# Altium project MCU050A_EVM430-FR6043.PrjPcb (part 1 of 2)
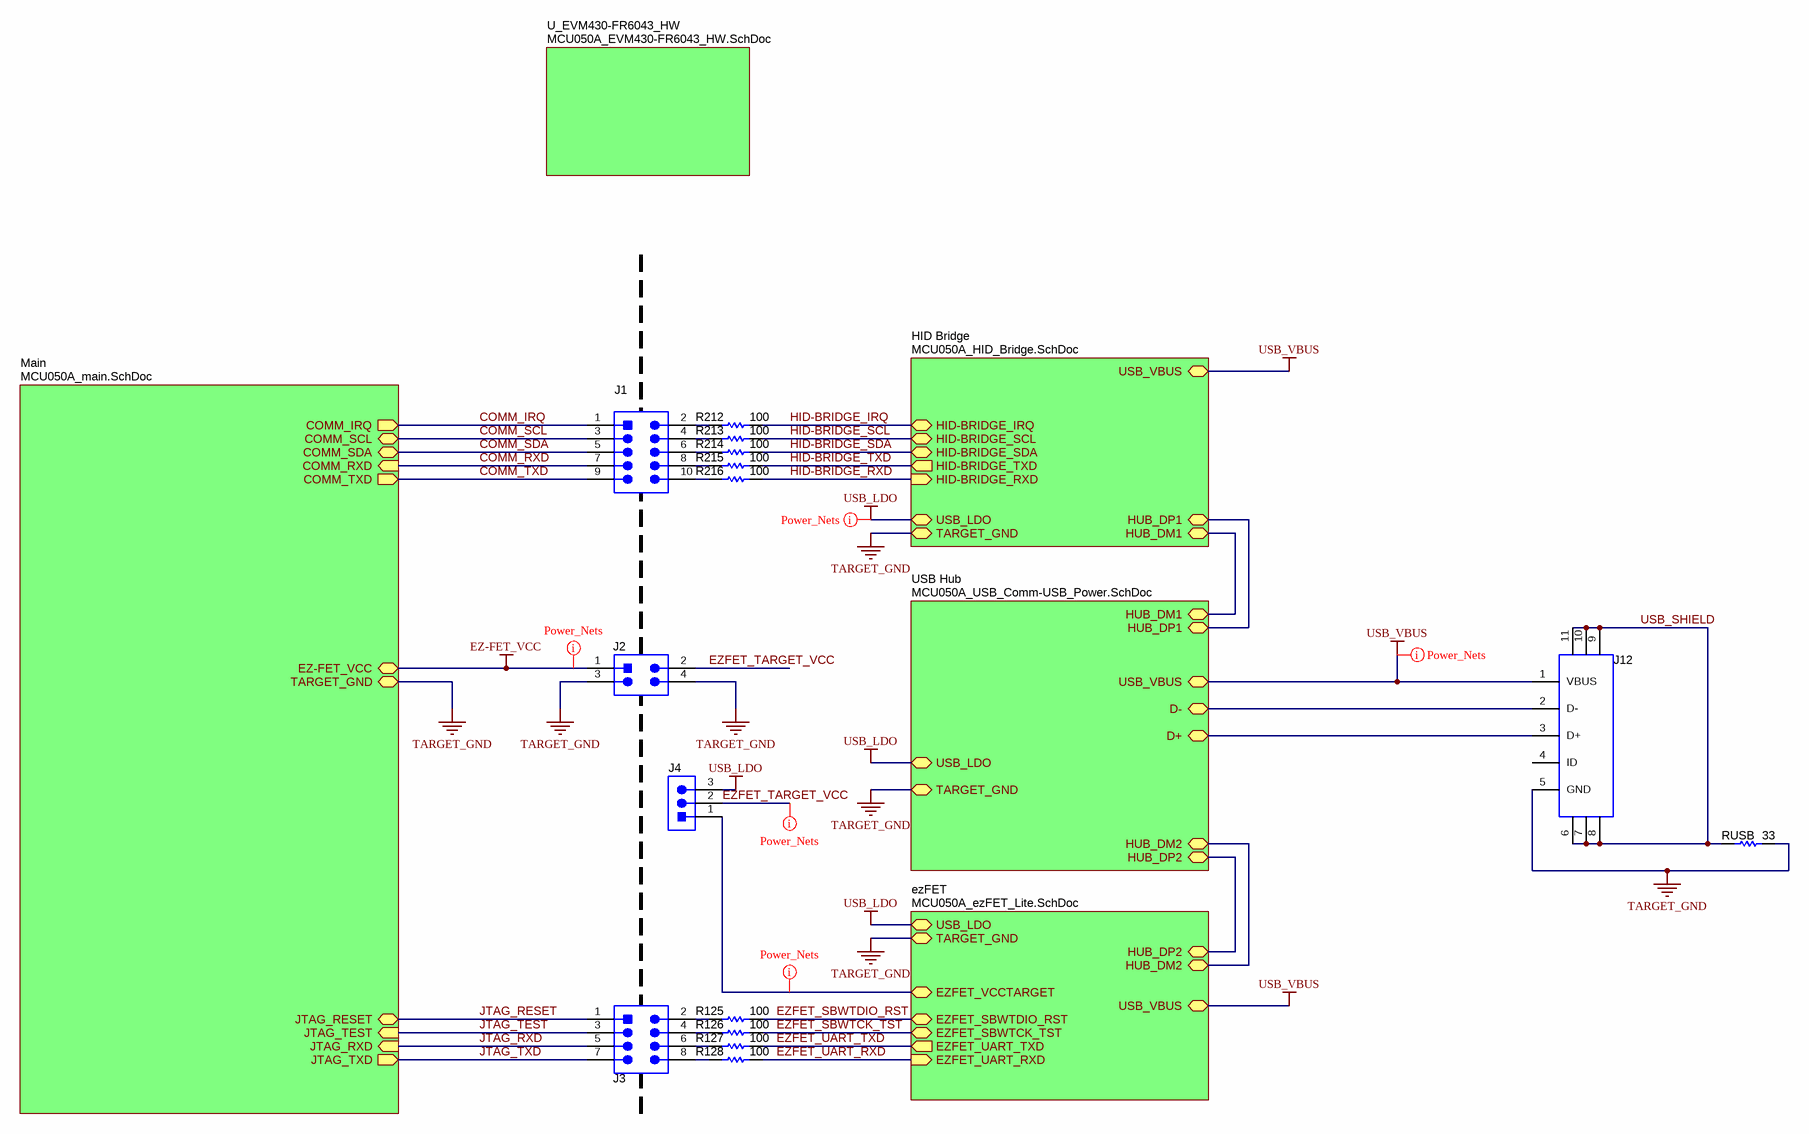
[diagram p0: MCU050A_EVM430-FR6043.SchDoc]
CopyrightYear: 2017; PCB_Layout: D. Garcia; PCB_Rev: A; PRJ_Customer: Public Release; PRJ_Engineer: D. Garcia; PRJ_Number: MCU050; PRJ_Title: EVM430-FR6043; SCH_Rev: A; TechSupport: http://www.ti.com/support; TID: N/A
7 sheets, 336 parts. Net scope: hierarchical (ports join the sheet entries above them; power ports are global).
Board file: MCU050A_EVM430-FR6043.PcbDoc
Sheets:
  MCU050A_EVM430-FR6043.SchDoc
    U_EVM430-FR6043_HW = MCU050A_EVM430-FR6043_HW.SchDoc
    Main = MCU050A_main.SchDoc
      AFE = MCU050A_Analog-Front-End.SchDoc
    HID Bridge = MCU050A_HID_Bridge.SchDoc
    USB Hub = MCU050A_USB_Comm-USB_Power.SchDoc
    ezFET = MCU050A_ezFET_Lite.SchDoc

## Sheet MCU050A_EVM430-FR6043.SchDoc
size 431 x 279 mm; Date: Not shown in title block; ApprovedBy: Not shown in title block; CheckedBy: Not shown in title block; Author: Not shown in title block; CompanyName: Not shown in title block; Engineer: Not shown in title block; Organization: Not shown in title block; Address1: Not shown in title block; Address2: Not shown in title block; Address3: Not shown in title block; Address4: Not shown in title block; DocumentNumber: 1; Revision: Use project parameter SCH_Rev; SheetNumber: 1; SheetTotal: 7; PageSetup: Record=PageOptions¦CenterHorizontal=True¦CenterVertical=True¦PrintScale=1.00¦XCorrection=1.00¦YCorrection=1.00¦PrintKind=0¦BorderSize=5000000¦LeftOffset=0¦BottomOffset=0¦Orientation=2¦PaperLength=1000¦PaperWidth=1000¦Scale=100¦PaperSource=15¦PrintQuality=600¦MediaType=1¦DitherType=10¦PaperKind=Letter¦PrintScaleMode=1

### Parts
J1  TSW-105-07-G-D  [TSW-105-07-G-D]  (value not drawn)
J2  PBC02DAAN  [Sullins_PxC02DAAN]  (value not drawn)
J3  PEC04DAAN  [CONN_PEC04DAAN]  (value not drawn)
J4  61300311121  [WURTH_61300311121]  (value not drawn)
J12  1051640001  [Molex_1051640001]  (value not drawn)
R125  ValueDisplayed: 100  [0402S]  (hidden comment: CRCW0402100RJNED)
R126  ValueDisplayed: 100  [0402S]  (hidden comment: CRCW0402100RJNED)
R127  ValueDisplayed: 100  [0402S]  (hidden comment: CRCW0402100RJNED)
R128  ValueDisplayed: 100  [0402S]  (hidden comment: CRCW0402100RJNED)
R212  ValueDisplayed: 100  [0402S]  (hidden comment: CRCW0402100RJNED)
R213  ValueDisplayed: 100  [0402S]  (hidden comment: CRCW0402100RJNED)
R214  ValueDisplayed: 100  [0402S]  (hidden comment: CRCW0402100RJNED)
R215  ValueDisplayed: 100  [0402S]  (hidden comment: CRCW0402100RJNED)
R216  ValueDisplayed: 100  [0402S]  (hidden comment: CRCW0402100RJNED)
RUSB  value 33  [0402S]  (hidden comment: CRCW040233R0JNED)

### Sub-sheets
ezFET = MCU050A_ezFET_Lite.SchDoc: EZFET_SBWTDIO_RST (bidir), EZFET_SBWTCK_TST (bidir), EZFET_UART_TXD (out), EZFET_UART_RXD (in), HUB_DP2 (bidir), HUB_DM2 (bidir), USB_VBUS, TARGET_GND, USB_LDO, EZFET_VCCTARGET
HID Bridge = MCU050A_HID_Bridge.SchDoc: HID-BRIDGE_TXD (out), HID-BRIDGE_RXD (in), HID-BRIDGE_SCL (bidir), HID-BRIDGE_SDA (bidir), HID-BRIDGE_IRQ (bidir), USB_VBUS, USB_LDO, TARGET_GND, HUB_DM1 (bidir), HUB_DP1 (bidir)
Main = MCU050A_main.SchDoc: COMM_RXD (in), COMM_TXD (out), COMM_SCL (bidir), COMM_SDA (bidir), EZ-FET_VCC, TARGET_GND, COMM_IRQ (out), JTAG_TXD (out), JTAG_RXD (in), JTAG_TEST (in), JTAG_RESET (bidir)
U_EVM430-FR6043_HW = MCU050A_EVM430-FR6043_HW.SchDoc: no entries
USB Hub = MCU050A_USB_Comm-USB_Power.SchDoc: HUB_DM1 (bidir), HUB_DP1 (bidir), HUB_DP2 (bidir), HUB_DM2 (bidir), USB_LDO, USB_VBUS, D- (bidir), D+ (bidir), TARGET_GND

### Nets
EZ-FET_VCC: J2.1 ; sheet Main/EZ-FET_VCC
TARGET_GND: J2.3 J2.4 J12.5(GND) RUSB.1 ; sheet Main/TARGET_GND, sheet HID Bridge/TARGET_GND, sheet USB Hub/TARGET_GND, sheet ezFET/TARGET_GND
USB_LDO: J4.3 ; sheet HID Bridge/USB_LDO, sheet USB Hub/USB_LDO, sheet ezFET/USB_LDO
USB_VBUS: J12.1(VBUS) ; sheet HID Bridge/USB_VBUS, sheet USB Hub/USB_VBUS, sheet ezFET/USB_VBUS
COMM_IRQ: J1.1 ; sheet Main/COMM_IRQ
COMM_RXD: J1.7 ; sheet Main/COMM_RXD
COMM_SCL: J1.3 ; sheet Main/COMM_SCL
COMM_SDA: J1.5 ; sheet Main/COMM_SDA
COMM_TXD: J1.9 ; sheet Main/COMM_TXD
D+: J12.3(D+) ; sheet USB Hub/D+
D-: J12.2(D-) ; sheet USB Hub/D-
EZFET_SBWTCK_TST: R126.1 ; sheet ezFET/EZFET_SBWTCK_TST
EZFET_SBWTDIO_RST: R125.1 ; sheet ezFET/EZFET_SBWTDIO_RST
EZFET_TARGET_VCC: J2.2 J4.2
EZFET_UART_RXD: R128.1 ; sheet ezFET/EZFET_UART_RXD
EZFET_UART_TXD: R127.1 ; sheet ezFET/EZFET_UART_TXD
EZFET_VCCTARGET: J4.1 ; sheet ezFET/EZFET_VCCTARGET
HID-BRIDGE_IRQ: R212.1 ; sheet HID Bridge/HID-BRIDGE_IRQ
HID-BRIDGE_RXD: R216.1 ; sheet HID Bridge/HID-BRIDGE_RXD
HID-BRIDGE_SCL: R213.1 ; sheet HID Bridge/HID-BRIDGE_SCL
HID-BRIDGE_SDA: R214.1 ; sheet HID Bridge/HID-BRIDGE_SDA
HID-BRIDGE_TXD: R215.1 ; sheet HID Bridge/HID-BRIDGE_TXD
HUB_DM1: sheet HID Bridge/HUB_DM1, sheet USB Hub/HUB_DM1
HUB_DM2: sheet USB Hub/HUB_DM2, sheet ezFET/HUB_DM2
HUB_DP1: sheet HID Bridge/HUB_DP1, sheet USB Hub/HUB_DP1
HUB_DP2: sheet USB Hub/HUB_DP2, sheet ezFET/HUB_DP2
JTAG_RESET: J3.1 ; sheet Main/JTAG_RESET
JTAG_RXD: J3.5 ; sheet Main/JTAG_RXD
JTAG_TEST: J3.3 ; sheet Main/JTAG_TEST
JTAG_TXD: J3.7 ; sheet Main/JTAG_TXD
USB_SHIELD: J12.6 J12.7 J12.8 J12.9 J12.10 J12.11 RUSB.2
NetJ1_2: J1.2 R212.2
NetJ1_4: J1.4 R213.2
NetJ1_6: J1.6 R214.2
NetJ1_8: J1.8 R215.2
NetJ1_10: J1.10 R216.2
NetJ3_2: J3.2 R125.2
NetJ3_4: J3.4 R126.2
NetJ3_6: J3.6 R127.2
NetJ3_8: J3.8 R128.2

Not connected (* = marked no-connect by the designer): J12 4(ID)

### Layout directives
net class Power_Nets: EZ-FET_VCC, EZFET_TARGET_VCC, EZFET_VCCTARGET, USB_LDO, USB_VBUS

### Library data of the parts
J1 = TSW-105-07-G-D: Header, 100mil, 5x2, Gold, TH; Manufacturer: Samtec; SymbolCreator: a0412235; Pitch_mm: 2.54; Gender: Male; Shrouded: N; Row_Count: 2; Current_A: 6.3; Voltage_V: 550; Cert_CSA: Y; Green_Lifecycle: Active; Green_REACh: Passed
J2 = PBC02DAAN: Header, 2.54mm, 2x2, Gold, TH; Manufacturer: Sullins Connector Solutions; SymbolCreator: a0412235; Pitch_mm: 2.54; Gender: Male; Shrouded: N; Row_Count: 2; Current_A: 3; Voltage_V: 1800; Cert_UL: Y
J3 = PEC04DAAN: Header, 100mil, 4x2, Tin, TH; Manufacturer: Sullins Connector Solutions; SymbolCreator: a0411947; Pitch_mm: 2.54; Gender: Male; Shrouded: N; Row_Count: 2; Current_A: 3; Voltage_V: 1800; Cert_UL: Y; Green_Lifecycle: Not Set; Green_REACh: Incomplete
J4 = 61300311121: Header, 2.54 mm, 3x1, Gold, TH; Manufacturer: Wurth Elektronik; SymbolCreator: a0799628; Green_Lifecycle: Active; Green_REACh: Passed
J12 = 1051640001: Receptacle, USB 2.0, Micro B, 5 Position, R/A, SMT; Manufacturer: Molex; SymbolCreator: a0411947; Pitch_mm: 0.65; Gender: Female; ContactFinish: Gold; Current_A: 1.8; Voltage_V: 30; Cert_UL: Y
R125-R128 R212-R216 = CRCW0402100RJNED: RES, 100, 5%, 0.063 W, 0402; Manufacturer: Vishay-Dale; CompType: Resistor; Value: 100; Value_Code: 100R; Tolerance_%: 5; Power_W: 0.063; Value2: 0.063W; VDC_V: 50; TempCo: 200 ppm/C; EIA_Code: E24; U/M: EA; AEC Category: Q200
RUSB = CRCW040233R0JNED: RES, 33 ohm, 5%, 0.063W, 0402; Manufacturer: Vishay-Dale; CompType: Resistor; Value_Code: 33R0; Tolerance_%: 5; Power_W: 0.063; VDC_V: 50; TempCo: 200 ppm/C; EIA_Code: E24; U/M: EA

## Sheet MCU050A_EVM430-FR6043_HW.SchDoc
size 431 x 279 mm; Date: Not shown in title block; ApprovedBy: Not shown in title block; CheckedBy: Not shown in title block; Author: Not shown in title block; CompanyName: Not shown in title block; DrawnBy: Michael Schneider; Engineer: Not shown in title block; Organization: Not shown in title block; Address1: Not shown in title block; Address2: Not shown in title block; Address3: Not shown in title block; Address4: Not shown in title block; DocumentNumber: 1; Revision: Use project parameter SCH_Rev; SheetNumber: 7; SheetTotal: 7; PageSetup: Record=PageOptions¦CenterHorizontal=True¦CenterVertical=True¦PrintScale=1.00¦XCorrection=1.00¦YCorrection=1.00¦PrintKind=0¦BorderSize=5000000¦LeftOffset=0¦BottomOffset=0¦Orientation=2¦PaperLength=1000¦PaperWidth=1000¦Scale=100¦PaperSource=15¦PrintQuality=600¦MediaType=1¦DitherType=10¦PaperKind=Letter¦PrintScaleMode=1
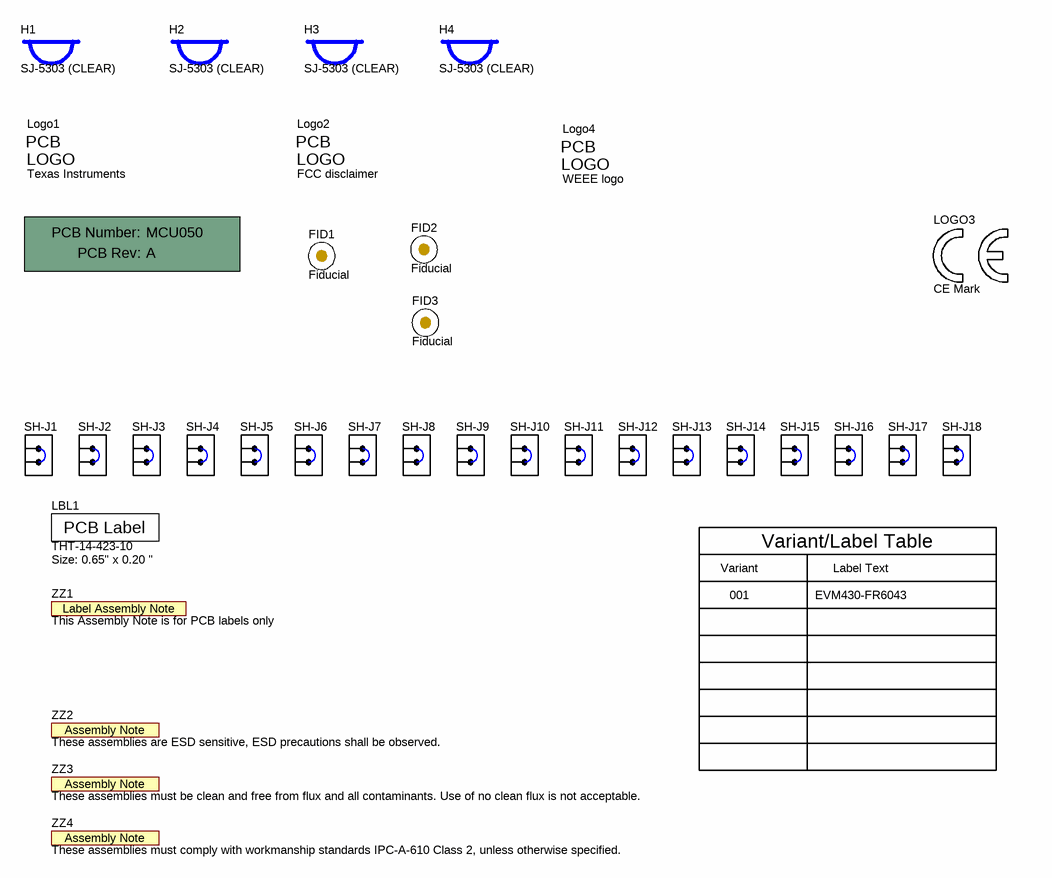
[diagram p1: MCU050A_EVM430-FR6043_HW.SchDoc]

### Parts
!PCB  Printed Circuit Board  (value not drawn)  (mechanical)
FID1  Fiducial  [Fiducial10-30]
FID2  Fiducial  [Fiducial10-30]
FID3  Fiducial  [Fiducial10-30]
H1  SJ-5303 (CLEAR)  [Bumpon_SJ5003Transparent]
H2  SJ-5303 (CLEAR)  [Bumpon_SJ5003Transparent]
H3  SJ-5303 (CLEAR)  [Bumpon_SJ5003Transparent]
H4  SJ-5303 (CLEAR)  [Bumpon_SJ5003Transparent]
LBL1  THT-14-423-10  Note: Size: 0.65" x 0.20 "  [Label_650x200]
Logo1  Texas Instruments  [TI_Stacked_Overlay_Small]  (no BOM)
Logo2  FCC disclaimer  [FCC_disclaimer]  (no BOM)
LOGO3  CE Mark  [CE_Mark_5mm]  (no BOM)
Logo4  WEEE logo  [WEEE_Minimum]  (no BOM)
SH-J1  60900213421  [Wurth_60900213421]  (value not drawn)
SH-J2  60900213421  [Wurth_60900213421]  (value not drawn)
SH-J3  60900213421  [Wurth_60900213421]  (value not drawn)
SH-J4  60900213421  [Wurth_60900213421]  (value not drawn)
SH-J5  60900213421  [Wurth_60900213421]  (value not drawn)
SH-J6  60900213421  [Wurth_60900213421]  (value not drawn)
SH-J7  60900213421  [Wurth_60900213421]  (value not drawn)
SH-J8  60900213421  [Wurth_60900213421]  (value not drawn)
SH-J9  60900213421  [Wurth_60900213421]  (value not drawn)
SH-J10  60900213421  [Wurth_60900213421]  (value not drawn)
SH-J11  60900213421  [Wurth_60900213421]  (value not drawn)
SH-J12  60900213421  [Wurth_60900213421]  (value not drawn)
SH-J13  60900213421  [Wurth_60900213421]  (value not drawn)
SH-J14  60900213421  [Wurth_60900213421]  (value not drawn)
SH-J15  60900213421  [Wurth_60900213421]  (value not drawn)
SH-J16  60900213421  [Wurth_60900213421]  (value not drawn)
SH-J17  60900213421  [Wurth_60900213421]  (value not drawn)
SH-J18  60900213421  [Wurth_60900213421]  (value not drawn)
ZZ1  This Assembly Note is for PCB labels only  [AssemblyNoteLabel]  (no BOM)
ZZ2  These assemblies are ESD sensitive, ESD precautions shall be observed.  [AssemblyNote]  (no BOM)
ZZ3  These assemblies must be clean and free from flux and all contaminants. Use of no clean flux is not acceptable.  [AssemblyNote]  (no BOM)
ZZ4  These assemblies must comply with workmanship standards IPC-A-610 Class 2, unless otherwise specified.  [AssemblyNote]  (no BOM)

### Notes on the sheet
- Variant/Label Table
- Variant
- 001
- Label Text
- EVM430-FR6043

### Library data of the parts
!PCB = PCB: Manufacturer: Any; PartNumber: MCU050; SymbolCreator: a0412235
FID1-FID3 = CMP-0077181-1: Fiducial mark.  There is nothing to buy or mount.
H1-H4 = SJ-5303 (CLEAR): Bumpon, Hemisphere, 0.44 X 0.20, Clear; Manufacturer: 3M; SymbolCreator: a0412235
LBL1 = CMP-0003625-1: Thermal Transfer Printable Labels, 0.650" W x 0.200" H - 10,000 per roll; Manufacturer: Brady; CompType: Label
Logo1 = TI_Logo: Texas Instrument Corporate Signature; SymbolCreator: codlsc
Logo2 = FCC_disclaimer: SymbolCreator: codlsc
LOGO3 = CMP-0074844-1: SymbolCreator: a0412235
Logo4 = CMP-0074769-1
SH-J1-SH-J18 = CMP-0003761-2: Shunt, 2.54mm, Gold, Black; Manufacturer: Wurth Elektronik
ZZ1 = AssemblyNoteLabel: SymbolCreator: a0412235
ZZ2-ZZ4 = AssemblyNote: SymbolCreator: codlsc

## Sheet MCU050A_main.SchDoc
size 558 x 381 mm; Date: Not shown in title block; ApprovedBy: Not shown in title block; CheckedBy: Not shown in title block; Author: Not shown in title block; CompanyName: Not shown in title block; Engineer: Not shown in title block; Organization: Not shown in title block; Address1: Not shown in title block; Address2: Not shown in title block; Address3: Not shown in title block; Address4: Not shown in title block; DocumentNumber: 1; Revision: Use project parameter SCH_Rev; SheetNumber: 2; SheetTotal: 7; PageSetup: Record=PageOptions¦CenterHorizontal=True¦CenterVertical=True¦PrintScale=1.00¦XCorrection=1.00¦YCorrection=1.00¦PrintKind=0¦BorderSize=5000000¦LeftOffset=0¦BottomOffset=0¦Orientation=2¦PaperLength=1000¦PaperWidth=1000¦Scale=100¦PaperSource=15¦PrintQuality=600¦MediaType=1¦DitherType=10¦PaperKind=Letter¦PrintScaleMode=1
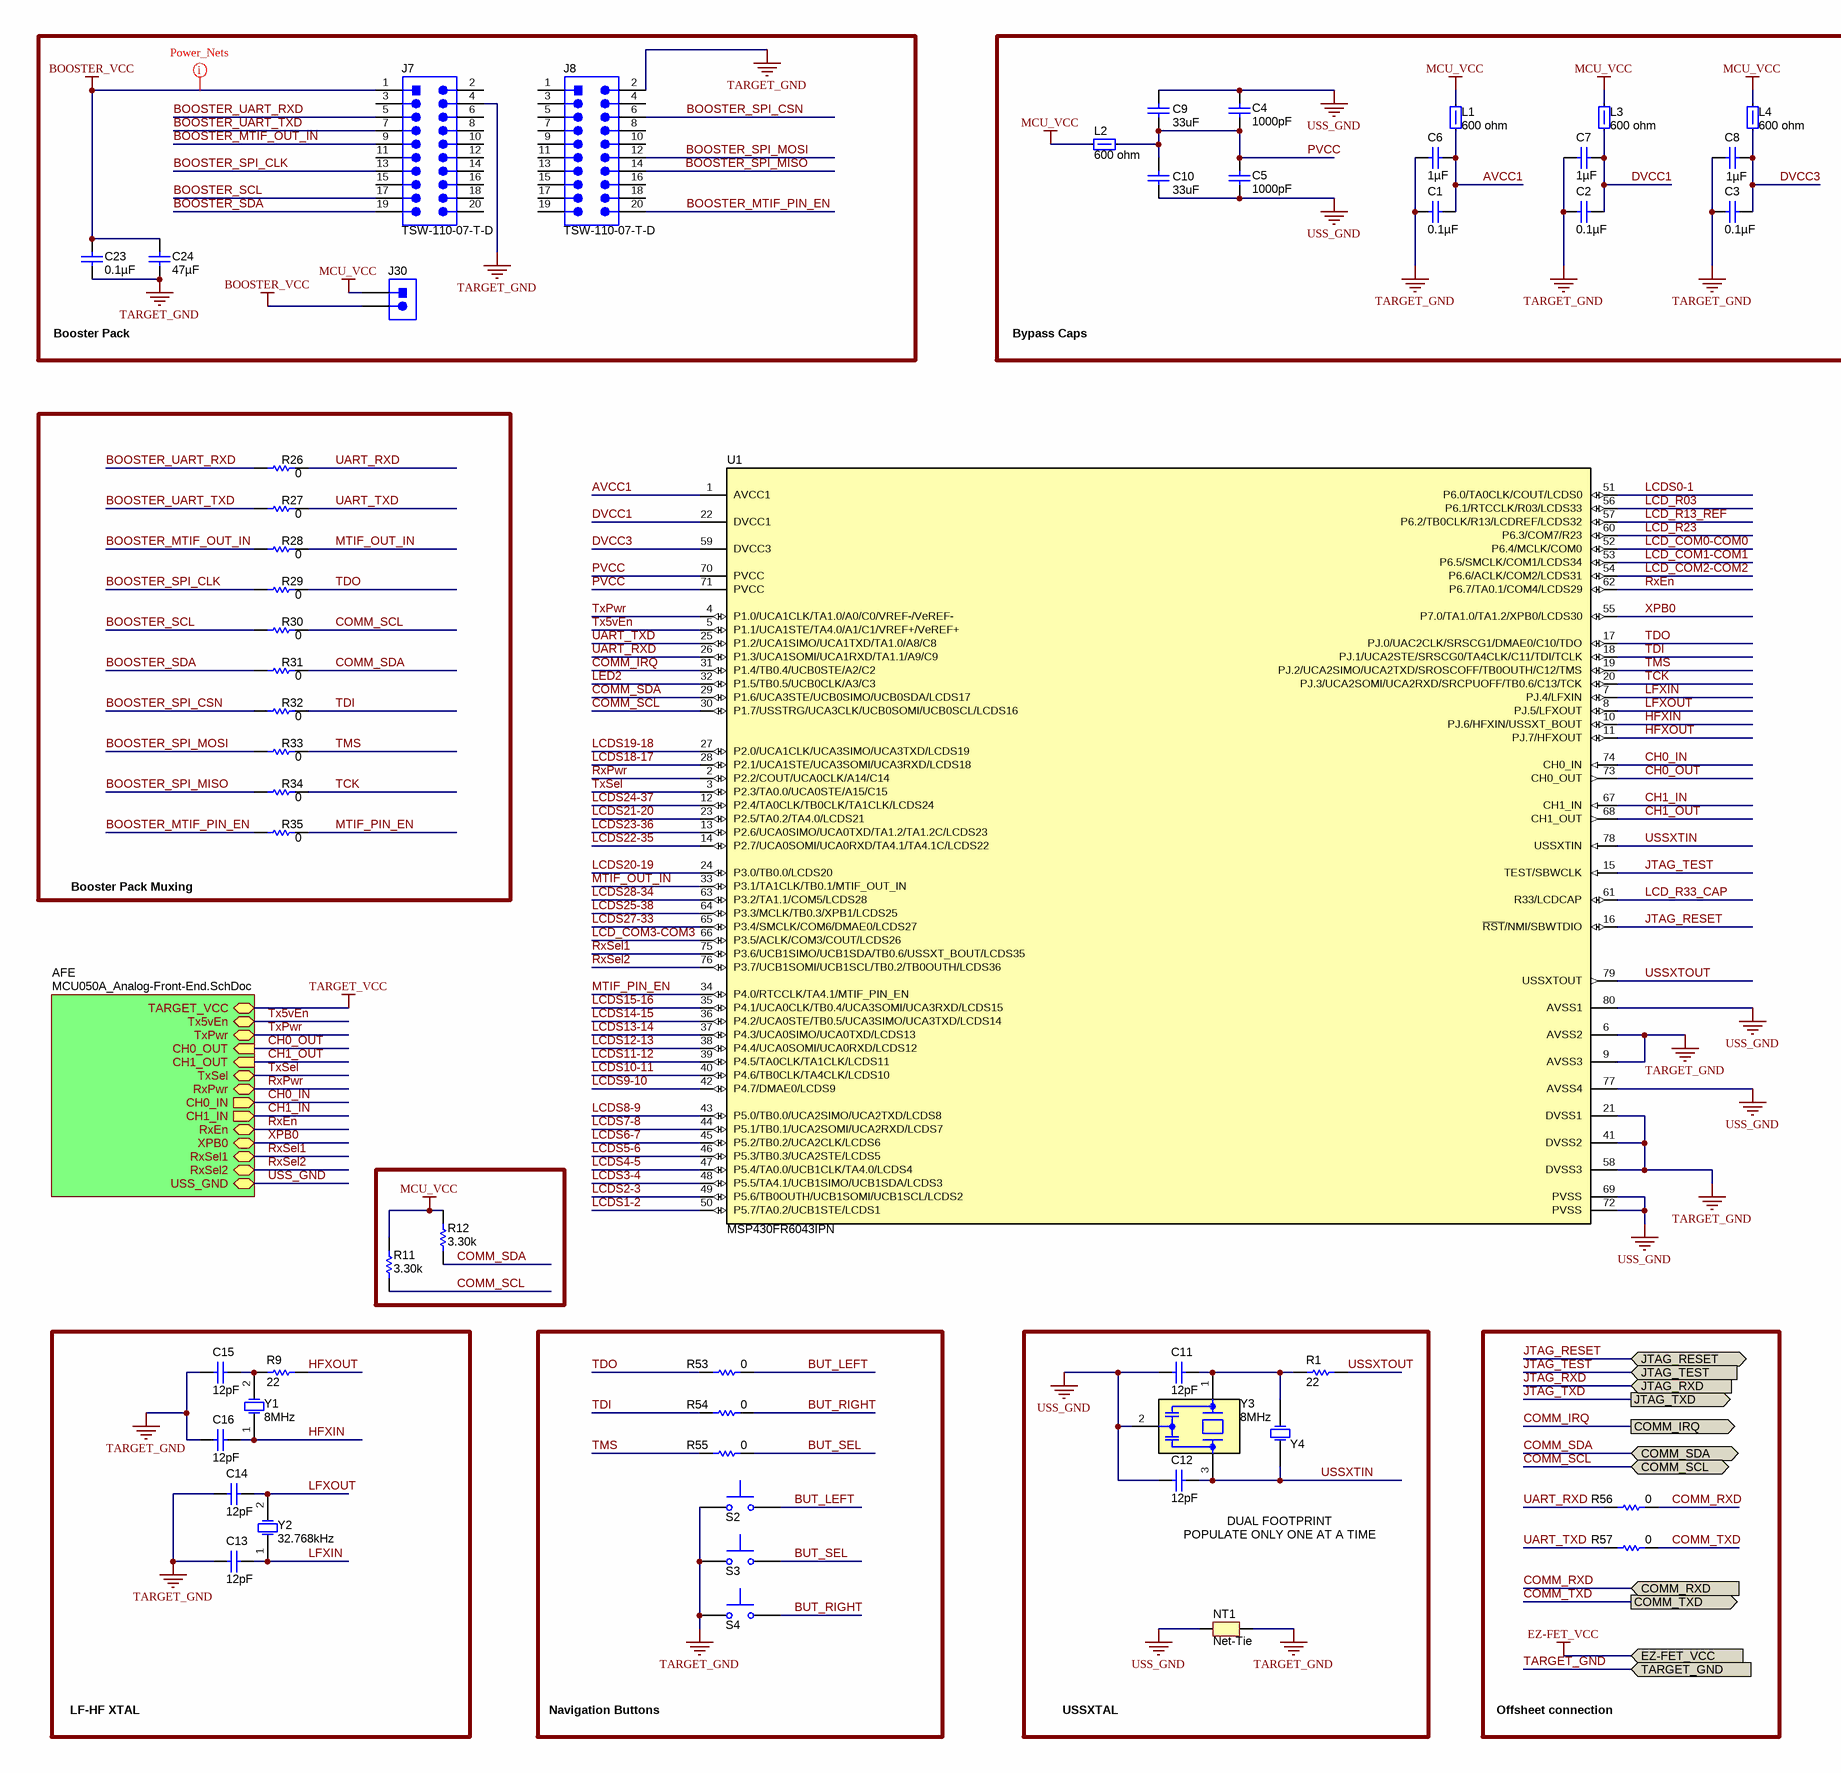
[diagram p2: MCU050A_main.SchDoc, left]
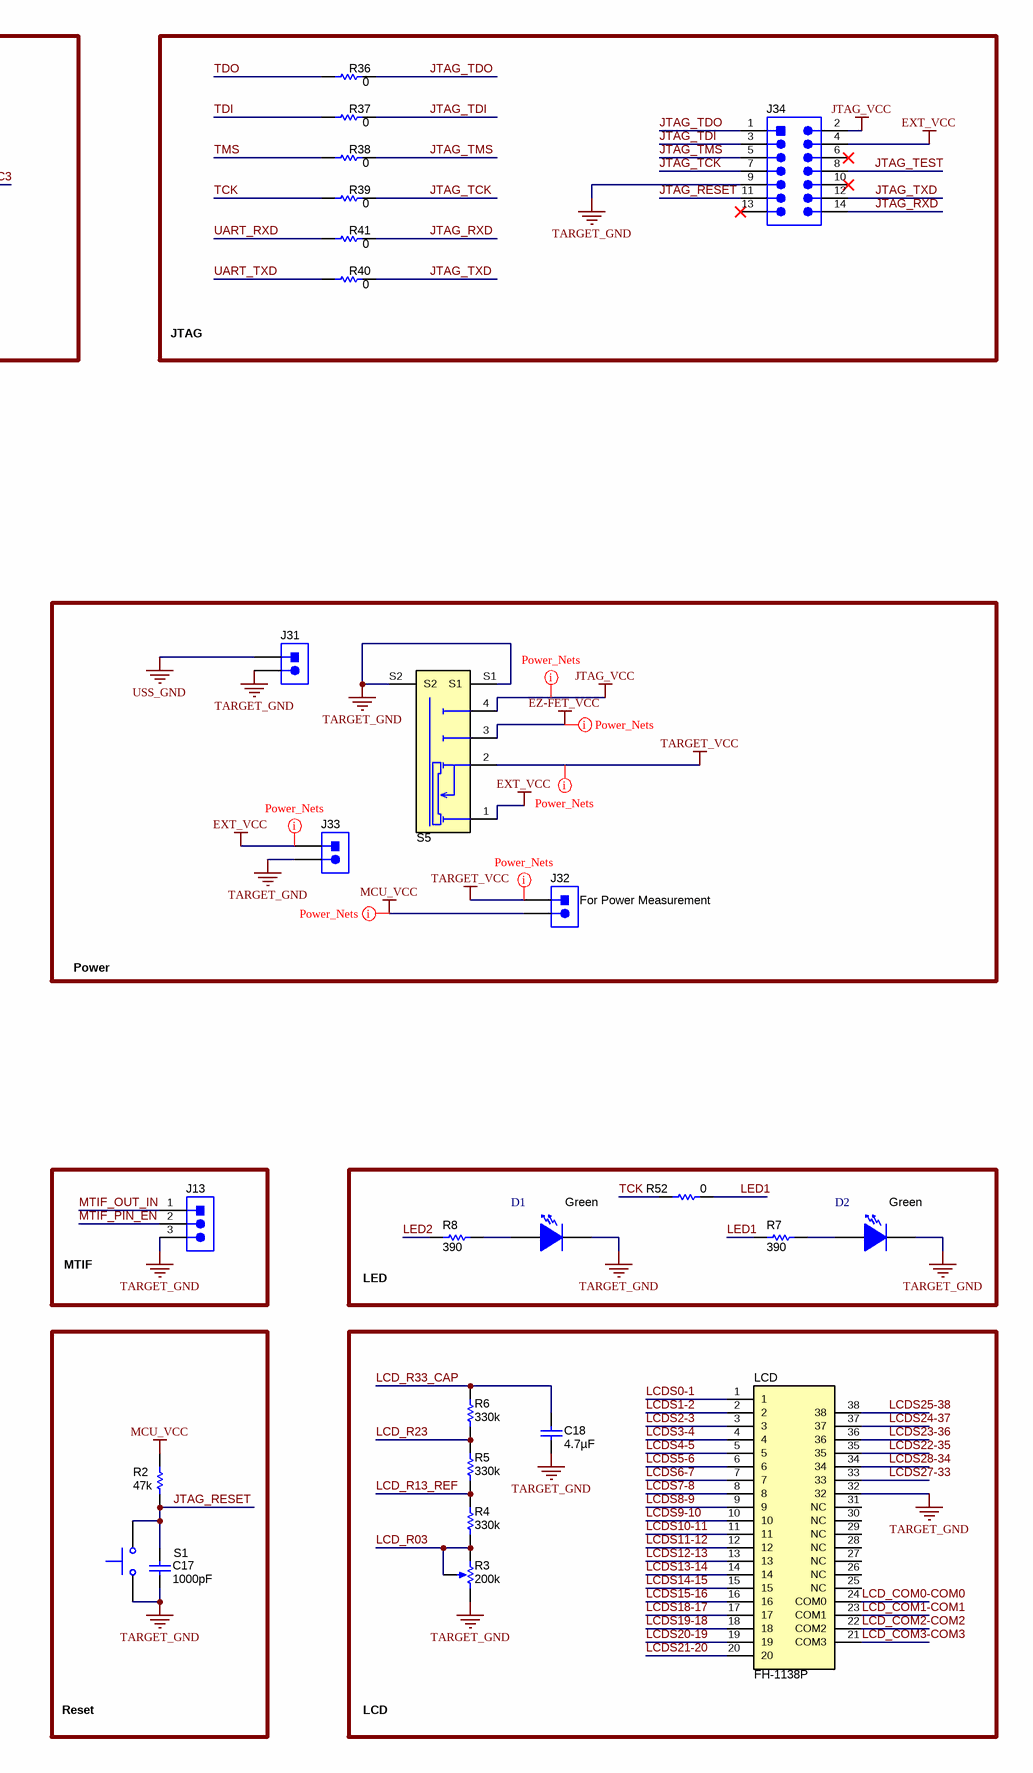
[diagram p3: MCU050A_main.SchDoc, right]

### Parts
C1  ValueDisplayed: 0.1µF  [0402S]  (hidden comment: GRM155R71C104KA88D)
C2  ValueDisplayed: 0.1µF  [0402S]  (hidden comment: GRM155R71C104KA88D)
C3  ValueDisplayed: 0.1µF  [0402S]  (hidden comment: GRM155R71C104KA88D)
C4  ValueDisplayed: 1000pF  [0402S]  (hidden comment: GRM1555C1H102JA01D)
C5  ValueDisplayed: 1000pF  [0402S]  (hidden comment: GRM1555C1H102JA01D)
C6  ValueDisplayed: 1µF  [0603S]  (hidden comment: GRM188R71A105KA61D)
C7  ValueDisplayed: 1µF  [0603S]  (hidden comment: GRM188R71A105KA61D)
C8  ValueDisplayed: 1µF  [0603S]  (hidden comment: GRM188R71A105KA61D)
C9  ValueDisplayed: 33uF  [0805]  (hidden comment: C2012X5R1A336M125AC)
C10  ValueDisplayed: 33uF  [0805]  (hidden comment: C2012X5R1A336M125AC)
C11  ValueDisplayed: 12pF  [0402]  (hidden comment: GRM1555C1H120JA01D)
C12  ValueDisplayed: 12pF  [0402]  (hidden comment: GRM1555C1H120JA01D)
C13  ValueDisplayed: 12pF  [0402S]  (hidden comment: GRM1555C1H120JA01D)
C14  ValueDisplayed: 12pF  [0402S]  (hidden comment: GRM1555C1H120JA01D)
C15  ValueDisplayed: 12pF  [0402]  (hidden comment: GRM1555C1H120JA01D)
C16  ValueDisplayed: 12pF  [0402]  (hidden comment: GRM1555C1H120JA01D)
C17  ValueDisplayed: 1000pF  [0402S]  (hidden comment: GRM1555C1H102JA01D)
C18  ValueDisplayed: 4.7µF  [0603M]  (hidden comment: GRM188R61A475MAAJ)
C23  ValueDisplayed: 0.1µF  [0402]  (hidden comment: GRM155R71C104KA88D)
C24  ValueDisplayed: 47µF  [0805_HV]  (hidden comment: GRM21BR60J476ME15L)
D1  value Green  [LTST-C191_Green]  (hidden comment: LTST-C191TGKT)
D2  value Green  [LTST-C191_Green]  (hidden comment: LTST-C191TGKT)
J7  TSW-110-07-T-D  [Samtec_TSW-110-07-x-D]
J8  TSW-110-07-T-D  [Samtec_TSW-110-07-x-D]
J13  61300311121  [WURTH_61300311121]  (value not drawn)
J30  61300211121  [WURTH_61300211121]  (value not drawn)
J31  61300211121  [WURTH_61300211121]  (value not drawn)
J32  61300211121  [WURTH_61300211121]  (value not drawn)
J33  61300211121  [WURTH_61300211121]  (value not drawn)
J34  SBH11-PBPC-D07-ST-BK  [CONN_SBH11-PBPC-D07-ST-BK]  (value not drawn)
L1  value 600 ohm  [0805L]  (hidden comment: MPZ2012S601A)
L2  value 600 ohm  [0805L]  (hidden comment: MPZ2012S601A)
L3  value 600 ohm  [0805L]  (hidden comment: MPZ2012S601A)
L4  value 600 ohm  [0805L]  (hidden comment: MPZ2012S601A)
LCD  FH-1138P  [ADKOM_FH-1138P]
NT1  Net-Tie  [Net-Tie_50milWide_30milLong]  (net tie, no BOM)
R1  ValueDisplayed: 22  [0402S]  (hidden comment: CRCW040222R0JNED)
R2  ValueDisplayed: 47k  [0402S]  (hidden comment: CRCW040247K0JNED)
R3  value 200k  [TRIM_3224W]  (hidden comment: 3224W-1-204E)
R4  ValueDisplayed: 330k  [0402S]  (hidden comment: CRCW0402330KJNED)
R5  ValueDisplayed: 330k  [0402S]  (hidden comment: CRCW0402330KJNED)
R6  ValueDisplayed: 330k  [0402S]  (hidden comment: CRCW0402330KJNED)
R7  ValueDisplayed: 390  [0402S]  (hidden comment: CRCW0402390RJNED)
R8  ValueDisplayed: 390  [0402S]  (hidden comment: CRCW0402390RJNED)
R9  ValueDisplayed: 22  [0402S]  (hidden comment: CRCW040222R0JNED)
R11  ValueDisplayed: 3.30k  [0402]  (hidden comment: ERJ-2RKF3301X)
R12  ValueDisplayed: 3.30k  [0402]  (hidden comment: ERJ-2RKF3301X)
R26  ValueDisplayed: 0  [0402S]  (hidden comment: CRCW04020000Z0ED)
R27  ValueDisplayed: 0  [0402S]  (hidden comment: CRCW04020000Z0ED)
R28  ValueDisplayed: 0  [0402S]  (hidden comment: CRCW04020000Z0ED)
R29  ValueDisplayed: 0  [0402S]  (hidden comment: CRCW04020000Z0ED)
R30  ValueDisplayed: 0  [0402S]  (hidden comment: CRCW04020000Z0ED)
R31  ValueDisplayed: 0  [0402S]  (hidden comment: CRCW04020000Z0ED)
R32  ValueDisplayed: 0  [0402S]  (hidden comment: CRCW04020000Z0ED)
R33  ValueDisplayed: 0  [0402S]  (hidden comment: CRCW04020000Z0ED)
R34  ValueDisplayed: 0  [0402S]  (hidden comment: CRCW04020000Z0ED)
R35  ValueDisplayed: 0  [0402S]  (hidden comment: CRCW04020000Z0ED)
R36  ValueDisplayed: 0  [0402S]  (hidden comment: CRCW04020000Z0ED)
R37  ValueDisplayed: 0  [0402S]  (hidden comment: CRCW04020000Z0ED)
R38  ValueDisplayed: 0  [0402S]  (hidden comment: CRCW04020000Z0ED)
R39  ValueDisplayed: 0  [0402S]  (hidden comment: CRCW04020000Z0ED)
R40  ValueDisplayed: 0  [0402S]  (hidden comment: CRCW04020000Z0ED)
R41  ValueDisplayed: 0  [0402S]  (hidden comment: CRCW04020000Z0ED)
R52  ValueDisplayed: 0  [0402S]  (hidden comment: CRCW04020000Z0ED)
R53  ValueDisplayed: 0  [0402S]  (hidden comment: CRCW04020000Z0ED)
R54  ValueDisplayed: 0  [0402S]  (hidden comment: CRCW04020000Z0ED)
R55  ValueDisplayed: 0  [0402S]  (hidden comment: CRCW04020000Z0ED)
R56  ValueDisplayed: 0  [0402S]  (hidden comment: CRCW04020000Z0ED)
R57  ValueDisplayed: 0  [0402S]  (hidden comment: CRCW04020000Z0ED)
S1  B3U-1000P  [SW_B3U-1000P]  (value not drawn)
S2  TL1015AF160QG  [SW_TL1015AF160QG]  (value not drawn)
S3  TL1015AF160QG  [SW_TL1015AF160QG]  (value not drawn)
S4  TL1015AF160QG  [SW_TL1015AF160QG]  (value not drawn)
S5  SS-13D16-VG 4 PA  [SW_SS-13D16-VG]  (value not drawn)
U1  MSP430FR6043IPN  [PN0080A_N]
Y1  Frequency: 8MHz  [Abracon_ABM3]  (hidden comment: ABM3-8.000MHZ-D2Y-T)
Y2  Frequency: 32.768kHz  [XTAL_ABS07]  (hidden comment: ABS07-32.768KHZ-9-T)
Y3  Frequency: 8MHz  [Abracon_AWSCR-CV]  (hidden comment: AWSCR-8.00CV-T)
Y4  ABLS-8.000MHZ-B4-T  [XTAL_CSM-7X]  (value not drawn)

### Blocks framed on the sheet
Booster Pack: C23 C24 J7 J8 J30
Bypass Caps: C1-C10 L1-L4
JTAG: J34 R36-R41
Booster Pack Muxing: R26-R35
MTIF: J13
LED: D1 D2 R7 R8 R52
LF-HF XTAL: C13-C16 R9 Y1 Y2
Navigation Buttons: R53-R55 S2-S4
Offsheet connection: R56 R57
Reset: C17 R2 S1
LCD: C18 LCD R3-R6

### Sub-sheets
AFE = MCU050A_Analog-Front-End.SchDoc: Tx5vEn (bidir), TxPwr (bidir), CH0_OUT (in), CH1_OUT (in), TxSel (bidir), RxPwr (bidir), CH0_IN (out), RxEn (bidir), XPB0 (bidir), RxSel1 (bidir), USS_GND, RxSel2 (bidir), CH1_IN (out), TARGET_VCC

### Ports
COMM_IRQ (out), COMM_RXD (in), COMM_SCL (bidir), COMM_SDA (bidir), COMM_TXD (out), EZ-FET_VCC, JTAG_RESET (bidir), JTAG_RXD (in), JTAG_TEST (in), JTAG_TXD (out), TARGET_GND

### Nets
BOOSTER_VCC: C23.1 C24.1 J7.1 J30.2
EXT_VCC: J33.1 J34.4 S5.1
EZ-FET_VCC: S5.3 ; port EZ-FET_VCC
JTAG_VCC: J34.2 S5.4
MCU_VCC: J30.1 J32.2 L1.2 L2.1 L3.2 L4.2 R2.2 R11.2 R12.2
TARGET_GND: C1.2 C2.1 C3.2 C6.2 C7.1 C8.1 C13.2 C14.1 C15.2 C16.2 C17.2 C18.2 C23.2 C24.2 D1.2(K) D2.2(K) J7.4 J8.2 J13.3 J31.2 J33.2 J34.9 LCD.32 NT1.2 R3.3(CW) S1.1 S2.1 S3.1 S4.1 S5.S1 S5.S2 U1.6(AVSS2) U1.9(AVSS3) U1.21(DVSS1) U1.41(DVSS2) U1.58(DVSS3) ; port TARGET_GND
TARGET_VCC: J32.1 S5.2 ; sheet AFE/TARGET_VCC
USS_GND: C4.1 C5.2 C9.1 C10.2 C11.2 C12.2 J31.1 NT1.1 U1.69(PVSS) U1.72(PVSS) U1.77(AVSS4) U1.80(AVSS1) Y3.2(GND) ; sheet AFE/USS_GND
AVCC1: C1.1 C6.1 L1.1 U1.1(AVCC1)
BOOSTER_MTIF_OUT_IN: J7.9 R28.2
BOOSTER_MTIF_PIN_EN: J8.20 R35.2
BOOSTER_SCL: J7.17 R30.2
BOOSTER_SDA: J7.19 R31.2
BOOSTER_SPI_CLK: J7.13 R29.2
BOOSTER_SPI_CSN: J8.6 R32.2
BOOSTER_SPI_MISO: J8.14 R34.2
BOOSTER_SPI_MOSI: J8.12 R33.2
BOOSTER_UART_RXD: J7.5 R26.2
BOOSTER_UART_TXD: J7.7 R27.2
BUT_LEFT: R53.1 S2.2
BUT_RIGHT: R54.1 S4.2
BUT_SEL: R55.1 S3.2
CH0_IN: U1.74(CH0_IN) ; sheet AFE/CH0_IN
CH0_OUT: U1.73(CH0_OUT) ; sheet AFE/CH0_OUT
CH1_IN: U1.67(CH1_IN) ; sheet AFE/CH1_IN
CH1_OUT: U1.68(CH1_OUT) ; sheet AFE/CH1_OUT
COMM_IRQ: U1.31(P1.4/TB0.4/UCB0STE/A2/C2) ; port COMM_IRQ
COMM_RXD: R56.1 ; port COMM_RXD
COMM_SCL: R11.1 R30.1 U1.30(P1.7/USSTRG/UCA3CLK/UCB0SOMI/UCB0SCL/LCDS16) ; port COMM_SCL
COMM_SDA: R12.1 R31.1 U1.29(P1.6/UCA3STE/UCB0SIMO/UCB0SDA/LCDS17) ; port COMM_SDA
COMM_TXD: R57.1 ; port COMM_TXD
DVCC1: C2.2 C7.2 L3.1 U1.22(DVCC1)
DVCC3: C3.1 C8.2 L4.1 U1.59(DVCC3)
HFXIN: C16.1 U1.10(PJ.6/HFXIN/USSXT_BOUT) Y1.1(OSC1)
HFXOUT: R9.2 U1.11(PJ.7/HFXOUT)
JTAG_RESET: C17.1 J34.11 R2.1 S1.2 U1.16(~{RST}/NMI/SBWTDIO) ; port JTAG_RESET
JTAG_RXD: J34.14 R41.1 ; port JTAG_RXD
JTAG_TCK: J34.7 R39.1
JTAG_TDI: J34.3 R37.1
JTAG_TDO: J34.1 R36.1
JTAG_TEST: J34.8 U1.15(TEST/SBWCLK) ; port JTAG_TEST
JTAG_TMS: J34.5 R38.1
JTAG_TXD: J34.12 R40.1 ; port JTAG_TXD
LCD_COM0-COM0: LCD.24(COM0) U1.52(P6.4/MCLK/COM0)
LCD_COM1-COM1: LCD.23(COM1) U1.53(P6.5/SMCLK/COM1/LCDS34)
LCD_COM2-COM2: LCD.22(COM2) U1.54(P6.6/ACLK/COM2/LCDS31)
LCD_COM3-COM3: LCD.21(COM3) U1.66(P3.5/ACLK/COM3/COUT/LCDS26)
LCD_R03: R3.1(CCW) R3.2(WIPER) R4.2 U1.56(P6.1/RTCCLK/R03/LCDS33)
LCD_R13_REF: R4.1 R5.1 U1.57(P6.2/TB0CLK/R13/LCDREF/LCDS32)
LCD_R23: R5.2 R6.1 U1.60(P6.3/COM7/R23)
LCD_R33_CAP: C18.1 R6.2 U1.61(R33/LCDCAP)
LCDS0-1: LCD.1 U1.51(P6.0/TA0CLK/COUT/LCDS0)
LCDS1-2: LCD.2 U1.50(P5.7/TA0.2/UCB1STE/LCDS1)
LCDS2-3: LCD.3 U1.49(P5.6/TB0OUTH/UCB1SOMI/UCB1SCL/LCDS2)
LCDS3-4: LCD.4 U1.48(P5.5/TA4.1/UCB1SIMO/UCB1SDA/LCDS3)
LCDS4-5: LCD.5 U1.47(P5.4/TA0.0/UCB1CLK/TA4.0/LCDS4)
LCDS5-6: LCD.6 U1.46(P5.3/TB0.3/UCA2STE/LCDS5)
LCDS6-7: LCD.7 U1.45(P5.2/TB0.2/UCA2CLK/LCDS6)
LCDS7-8: LCD.8 U1.44(P5.1/TB0.1/UCA2SOMI/UCA2RXD/LCDS7)
LCDS8-9: LCD.9 U1.43(P5.0/TB0.0/UCA2SIMO/UCA2TXD/LCDS8)
LCDS9-10: LCD.10 U1.42(P4.7/DMAE0/LCDS9)
LCDS10-11: LCD.11 U1.40(P4.6/TB0CLK/TA4CLK/LCDS10)
LCDS11-12: LCD.12 U1.39(P4.5/TA0CLK/TA1CLK/LCDS11)
LCDS12-13: LCD.13 U1.38(P4.4/UCA0SOMI/UCA0RXD/LCDS12)
LCDS13-14: LCD.14 U1.37(P4.3/UCA0SIMO/UCA0TXD/LCDS13)
LCDS14-15: LCD.15 U1.36(P4.2/UCA0STE/TB0.5/UCA3SIMO/UCA3TXD/LCDS14)
LCDS15-16: LCD.16 U1.35(P4.1/UCA0CLK/TB0.4/UCA3SOMI/UCA3RXD/LCDS15)
LCDS18-17: LCD.17 U1.28(P2.1/UCA1STE/UCA3SOMI/UCA3RXD/LCDS18)
LCDS19-18: LCD.18 U1.27(P2.0/UCA1CLK/UCA3SIMO/UCA3TXD/LCDS19)
LCDS20-19: LCD.19 U1.24(P3.0/TB0.0/LCDS20)
LCDS21-20: LCD.20 U1.23(P2.5/TA0.2/TA4.0/LCDS21)
LCDS22-35: LCD.35 U1.14(P2.7/UCA0SOMI/UCA0RXD/TA4.1/TA4.1C/LCDS22)
LCDS23-36: LCD.36 U1.13(P2.6/UCA0SIMO/UCA0TXD/TA1.2/TA1.2C/LCDS23)
LCDS24-37: LCD.37 U1.12(P2.4/TA0CLK/TB0CLK/TA1CLK/LCDS24)
LCDS25-38: LCD.38 U1.64(P3.3/MCLK/TB0.3/XPB1/LCDS25)
LCDS27-33: LCD.33 U1.65(P3.4/SMCLK/COM6/DMAE0/LCDS27)
LCDS28-34: LCD.34 U1.63(P3.2/TA1.1/COM5/LCDS28)
LED1: R7.1 R52.1
LED2: R8.1 U1.32(P1.5/TB0.5/UCB0CLK/A3/C3)
LFXIN: C13.1 U1.7(PJ.4/LFXIN) Y2.1(OSC1)
LFXOUT: C14.2 U1.8(PJ.5/LFXOUT) Y2.2(OSC2)
MTIF_OUT_IN: J13.1 R28.1 U1.33(P3.1/TA1CLK/TB0.1/MTIF_OUT_IN)
MTIF_PIN_EN: J13.2 R35.1 U1.34(P4.0/RTCCLK/TA4.1/MTIF_PIN_EN)
PVCC: C4.2 C5.1 C9.2 C10.1 L2.2 U1.70(PVCC) U1.71(PVCC)
RxEn: U1.62(P6.7/TA0.1/COM4/LCDS29) ; sheet AFE/RxEn
RxPwr: U1.2(P2.2/COUT/UCA0CLK/A14/C14) ; sheet AFE/RxPwr
RxSel1: U1.75(P3.6/UCB1SIMO/UCB1SDA/TB0.6/USSXT_BOUT/LCDS35) ; sheet AFE/RxSel1
RxSel2: U1.76(P3.7/UCB1SOMI/UCB1SCL/TB0.2/TB0OUTH/LCDS36) ; sheet AFE/RxSel2
TCK: R34.1 R39.2 R52.2 U1.20(PJ.3/UCA2SOMI/UCA2RXD/SRCPUOFF/TB0.6/C13/TCK)
TDI: R32.1 R37.2 R54.2 U1.18(PJ.1/UCA2STE/SRSCG0/TA4CLK/C11/TDI/TCLK)
TDO: R29.1 R36.2 R53.2 U1.17(PJ.0/UAC2CLK/SRSCG1/DMAE0/C10/TDO)
TMS: R33.1 R38.2 R55.2 U1.19(PJ.2/UCA2SIMO/UCA2TXD/SROSCOFF/TB0OUTH/C12/TMS)
Tx5vEn: U1.5(P1.1/UCA1STE/TA4.0/A1/C1/VREF+/VeREF+) ; sheet AFE/Tx5vEn
TxPwr: U1.4(P1.0/UCA1CLK/TA1.0/A0/C0/VREF-/VeREF-) ; sheet AFE/TxPwr
TxSel: U1.3(P2.3/TA0.0/UCA0STE/A15/C15) ; sheet AFE/TxSel
UART_RXD: R26.1 R41.2 R56.2 U1.26(P1.3/UCA1SOMI/UCA1RXD/TA1.1/A9/C9)
UART_TXD: R27.1 R40.2 R57.2 U1.25(P1.2/UCA1SIMO/UCA1TXD/TA1.0/A8/C8)
USSXTIN: C12.1 U1.78(USSXTIN) Y3.3(Out) Y4.1(OSC1)
USSXTOUT: R1.2 U1.79(USSXTOUT)
XPB0: U1.55(P7.0/TA1.0/TA1.2/XPB0/LCDS30) ; sheet AFE/XPB0
NetC11_1: C11.1 R1.1 Y3.1(In) Y4.2(OSC2)
NetC15_1: C15.1 R9.1 Y1.2(OSC2)
NetD1_1: D1.1(A) R8.2
NetD2_1: D2.1(A) R7.2

Not connected (* = marked no-connect by the designer): J7 2 3 6 8 10 11 12 14 15 16 18 20; J8 1 3 4 5 7 8 9 10 11 13 15 16 17 18 19; J34 6* 10* 13*; LCD 25(NC) 26(NC) 27(NC) 28(NC) 29(NC) 30(NC) 31(NC)

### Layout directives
net class Power_Nets: BOOSTER_VCC, EXT_VCC, EZ-FET_VCC, JTAG_VCC, MCU_VCC, TARGET_VCC

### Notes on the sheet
- (near J32) For Power Measurement
- Power
- DUAL FOOTPRINT
- POPULATE ONLY ONE AT A TIME
- USSXTAL

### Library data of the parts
C1-C3 = GRM155R71C104KA88D: CAP, CERM, 0.1 µF, 16 V, +/- 10%, X7R, 0402; Manufacturer: MuRata; Value: 0.1uF; Polarized: N; CompType: Capacitor; U/M: EA; Cap_F: 0.0000001; Tolerance_%: 10; Value1: Unknown; VDC_V: 16; Value2: 16V; TaMin_C: -55; TaMax_C: 125; Cap_Case: 0402; AEC Category: Q200
C4 C5 C17 = GRM1555C1H102JA01D: CAP, CERM, 1000 pF, 50 V, +/- 5%, C0G/NP0, 0402; Manufacturer: MuRata; Value: 1000pF; Polarized: N; CompType: Capacitor; U/M: EA; Cap_F: 0.000000001; Tolerance_%: 5; Value1: Unknown; VDC_V: 50; Value2: 50V; TaMin_C: -55; TaMax_C: 125; Cap_Case: 0402; AEC Category: Q200
C6 = GRM188R71A105KA61D: CAP, CERM, 1 µF, 10 V, +/- 10%, X7R, 0603; Manufacturer: MuRata; Polarized: N; CompType: Capacitor; Value: 1uF; U/M: EA; Cap_F: 0.000001; Tolerance_%: 10; ESR_ohm: 0.011; Value1: 0.011 ohm; Value2: 10V; TaMin_C: -55; TaMax_C: 125; Cap_Case: 0603; AEC Category: Q200; SizeArea_mm2: 1.28; SizeAreaWB_mm2: 4.68; SizeX_mm: 1.6; SizeY_mm: 0.8; SizeZ_mm: 1
C7 C8 = GRM188R71A105KA61D: CAP, CERM, 1 µF, 10 V, +/- 10%, X7R, 0603; Manufacturer: MuRata; Polarized: N; CompType: Capacitor; Value: 1uF; U/M: EA; Cap_F: 0.000001; Tolerance_%: 10; ESR_ohm: 0.011; Value1: 0.011 ohm; Value2: 10V; TaMin_C: -55; TaMax_C: 125; Cap_Case: 0603; SizeArea_mm2: 1.28; SizeAreaWB_mm2: 4.68; SizeX_mm: 1.6; SizeY_mm: 0.8; SizeZ_mm: 1; AEC Category: Q200
C9 C10 = CMP-0007824-2: CAP, CERM, 33 uF, 10 V, +/- 20%, X5R, 0805; Manufacturer: TDK; TaMin_C: -55°C; ESR_ohm: 1.694m; Polarized: N; SizeAreaWB_mm2: 6.75; Value1: 0.001694 ohm; U/M: EA; Value: 33uF; TaMax_C: 85°C; SizeZ_mm: 1.45; SizeX_mm: 2; SizeY_mm: 1.25; Value2: 10V; SizeArea_mm2: 2.5; CompType: Capacitor; Cap_F: 33µF; IRMS_A: 5.01281A; AEC Category: Q200
C11 C12 C15 C16 = GRM1555C1H120JA01D: CAP, CERM, 12 pF, 50 V, +/- 5%, C0G/NP0, 0402; Manufacturer: MuRata; Polarized: N; CompType: Capacitor; Value: 12pF; U/M: EA; Cap_F: 0.000000000012; Tolerance_%: 5; Value1: Unknown; VDC_V: 50; Value2: 50V; TaMin_C: -55; TaMax_C: 125; SizeArea_mm2: 0.5; SizeAreaWB_mm2: 3; SizeX_mm: 1; SizeZ_mm: 0.6; AEC Category: Q200
C13 C14 = GRM1555C1H120JA01D: CAP, CERM, 12 pF, 50 V, +/- 5%, C0G/NP0, 0402; Manufacturer: MuRata; Value: 12pF; Polarized: N; CompType: Capacitor; U/M: EA; Cap_F: 0.000000000012; Tolerance_%: 5; Value1: Unknown; VDC_V: 50; Value2: 50V; TaMin_C: -55; TaMax_C: 125; Cap_Case: 0402; AEC Category: Q200
C18 = GRM188R61A475MAAJ: CAP, CERM, 4.7 µF, 10 V, +/- 20%, X5R, 0603; Manufacturer: MuRata; Polarized: N; CompType: Capacitor; Value: 4.7uF; U/M: EA; Cap_F: 0.0000047; Tolerance_%: 20; Value1: Unknown; VDC_V: 10; Value2: 10V; TaMin_C: -55; TaMax_C: 85; Cap_Case: 0603; AEC Category: Q200
C23 = GRM155R71C104KA88D: CAP, CERM, 0.1 µF, 16 V, +/- 10%, X7R, 0402; Manufacturer: MuRata; Polarized: N; CompType: Capacitor; Value: 0.1uF; U/M: EA; Cap_F: 0.0000001; Tolerance_%: 10; Value1: Unknown; VDC_V: 16; Value2: 16V; TaMin_C: -55; TaMax_C: 125; SizeArea_mm2: 0.5; SizeAreaWB_mm2: 3; SizeX_mm: 1; SizeZ_mm: 0.6; AEC Category: Q200
C24 = GRM21BR60J476ME15L: CAP, CERM, 47 µF, 6.3 V, +/- 20%, X5R, 0805; Manufacturer: MuRata; Polarized: N; CompType: Capacitor; Value: 47uF; U/M: EA; Cap_F: 0.000047; Tolerance_%: 20; Value1: Unknown; VDC_V: 6.3; Value2: 6.3V; TaMin_C: -55; TaMax_C: 85; Cap_Case: 0805; SizeArea_mm2: 2.5; SizeAreaWB_mm2: 6.75; SizeX_mm: 2; SizeY_mm: 1.25; SizeZ_mm: 1.45; AEC Category: Q200
D1 D2 = LTST-C191TGKT: LED, Green, SMD; Manufacturer: Lite-On; Type: InGaN; Vf_V: 3.2; Value2: 3.2V; Io_A: 0.02; Value1: W; U/M: EA
J7 J8 = CMP-0075628-1: Header, 10x2, 2.54mm, Tin, TH; Manufacturer: Samtec; Pitch_mm: 2.54; Gender: Male; Cert_CSA: Y; Green_REACh: Passed; Voltage_V: 550V; CT: False; Shrouded: N; Green_Lifecycle: Active; Row_Count: 2; CNHeader: True
J13 = 61300311121: as J4 on sheet MCU050A_EVM430-FR6043
J30-J33 = 61300211121: Header, 2.54 mm, 2x1, Gold, TH; Manufacturer: Wurth Elektronik; SymbolCreator: a0412235; Green_Lifecycle: Active; Green_REACh: Passed
J34 = SBH11-PBPC-D07-ST-BK: Header (shrouded), 100 mil, 7x2, Gold, TH; Manufacturer: Sullins Connector Solutions; SymbolCreator: a0412235
L1-L4 = MPZ2012S601A: Ferrite Bead, 600 ohm @ 100 MHz, 2 A, 0805; Manufacturer: TDK; Alternate PartNumber: MPZ2012S601AT000; Imax_A: 2; DCR_ohm: 0.1; Value1: 0.1 ohm; Value2: 2A; ZTyp@100MHz_Ohm: 600
LCD = FH-1138P: 108 Segment LCD Display, TH; Manufacturer: Adkom Elektronik; SymbolCreator: Altium; SizeAreaWB_mm2: 1571.8; SizeArea_mm2: 1405.6; SizeX_mm: 25.1; SizeY_mm: 56; SizeZ_mm: 3.1
NT1 = Net-Tie: Single point connection between nets.; SymbolCreator: codlsc
R1 R9 = CRCW040222R0JNED: RES, 22, 5%, 0.063 W, 0402; Manufacturer: Vishay-Dale; Value: 22; CompType: Resistor; Value_Code: 22R0; Tolerance_%: 5; Power_W: 0.063; Value2: 0.063W; VDC_V: 50; TempCo: 200 ppm/C; EIA_Code: E24; U/M: EA; AEC Category: Q200
R2 = CRCW040247K0JNED: RES, 47 k, 5%, 0.063 W, 0402; Manufacturer: Vishay-Dale; Value: 47k; CompType: Resistor; Res_ohm: 47000; Value_Code: 47k0; Tolerance_%: 5; Power_W: 0.063; Value2: 0.063W; VDC_V: 50; TempCo: 200 ppm/C; EIA_Code: E24; U/M: EA
R3 = 3224W-1-204E: Trimmer, 200 K, 0.25 W, SMD; Manufacturer: Bourns; Sim Note: Enter the Resistance value and the set point into parameter fields.; SymbolCreator: a0412235
R4-R6 = CRCW0402330KJNED: RES, 330 k, 5%, 0.063 W, 0402; Manufacturer: Vishay-Dale; Value: 330k; CompType: Resistor; Res_ohm: 330000; Tolerance_%: 5; Power_W: 0.063; Value2: 0.063W; VDC_V: 50; TempCo: 200 ppm/C; EIA_Code: E24; U/M: EA; AEC Category: Q200
R7 R8 = CRCW0402390RJNED: RES, 390, 5%, 0.063 W, 0402; Manufacturer: Vishay-Dale; Value: 390; CompType: Resistor; Value_Code: 390R; Tolerance_%: 5; Power_W: 0.063; Value2: 0.063W; VDC_V: 50; TempCo: 200 ppm/C; EIA_Code: E24; U/M: EA; AEC Category: Q200
R11 R12 = ERJ-2RKF3301X: RES, 3.30 k, 1%, 0.1 W, AEC-Q200 Grade 0, 0402; Manufacturer: Panasonic; CompType: Resistor; Value: 3.30k; Res_ohm: 3300; Value_Code: 3k30; Tolerance_%: 1; Power_W: 0.1; Value2: 0.1W; VDC_V: 50; TempCo: 100 ppm/C; SizeArea_mm2: 0.5; SizeZ_mm: 0.6; U/M: EA; AEC Category: Q200; AEC Qualified: Y; AEC Grade: 0
R26-R41 R52-R57 = CRCW04020000Z0ED: RES, 0, 5%, 0.063 W, 0402; Manufacturer: Vishay-Dale; Value: 0; CompType: Resistor; Value_Code: 0000; Tolerance_%: 5; Power_W: 0.063; Value2: 0.063W; VDC_V: 50; TempCo: 200 ppm/C; EIA_Code: E24; U/M: EA
S1 = B3U-1000P: SWITCH TACTILE SPST-NO 0.05A 12V; Manufacturer: Omron Electronic Components; SymbolCreator: a0412235; VDC_V: 12; SwitchFunction: Off-Mom; PositionCount: 1; CurrentRating_mA: 50
S2-S4 = TL1015AF160QG: Switch, Tactile, SPST-NO, 0.05A, 12V, SMT; Manufacturer: E-Switch; SymbolCreator: a0412235; VDC_V: 12; SwitchFunction: Off-Mom; PositionCount: 1; CurrentRating_mA: 50
S5 = SS-13D16-VG 4 PA: Switch, Slide, SP3T, On-On-On, 3 Pos, 0.3A, 30 VDC, TH; Manufacturer: C&K Components; SymbolCreator: Altium; VDC_V: 30; PositionCount: 3; CurrentRating_mA: 300
U1 = CMP-0074889-1: Mixed-Signal Microcontroller, PN0080A (LQFP-80); Manufacturer: Texas Instruments; SizeZ_mm: 1.6; SizeX_mm: 14.0; SizeArea_mm2: 196.0; CompType: IC; U/M: EA; SizeAreaWB_mm2: 256.0
Y1 = ABM3-8.000MHZ-D2Y-T: Crystal, 8MHz, SMD; Manufacturer: Abracon Corporation; SymbolCreator: a0412235; U/M: EA; TaMin_C: -40; TaMax_C: 85; Frequency Stability: ±30ppm
Y2 = ABS07-32.768KHZ-9-T: CRYSTAL, 32.768KHZ, 9PF, SMD; Manufacturer: Abracon Corporation; SymbolCreator: a0412235; U/M: EA; TaMin_C: -40; TaMax_C: 85; Frequency Stability: ±20ppm
Y3 = AWSCR-8.00CV-T: Ceramic Resonator, 8MHz, 22pF, SMD; Manufacturer: Abracon Corporation; SymbolCreator: a0799721; SizeAreaWB_mm2: 19.27; SizeArea_mm2: 11.47; SizeX_mm: 3.7; SizeY_mm: 3.1; SizeZ_mm: 1.2; U/M: EA; TaMin_C: -25; TaMax_C: 85
Y4 = CMP-0004580-3: Crystal, 8 MHz, 18pF, SMD; Manufacturer: Abracon Corporation; TaMin_C: 0°C; Frequency Stability: +/-50ppm; Frequency_Fixed: 8MHz; TaMax_C: 70°C

## Sheet MCU050A_Analog-Front-End.SchDoc
size 431 x 279 mm; Date: Not shown in title block; ApprovedBy: Not shown in title block; CheckedBy: Not shown in title block; Author: Not shown in title block; CompanyName: Not shown in title block; Engineer: Not shown in title block; Organization: Not shown in title block; Address1: Not shown in title block; Address2: Not shown in title block; Address3: Not shown in title block; Address4: Not shown in title block; DocumentNumber: 1; Revision: Use project parameter SCH_Rev; SheetNumber: 3; SheetTotal: 7; PageSetup: Record=PageOptions¦CenterHorizontal=True¦CenterVertical=True¦PrintScale=1.00¦XCorrection=1.00¦YCorrection=1.00¦PrintKind=0¦BorderSize=5000000¦LeftOffset=0¦BottomOffset=0¦Orientation=2¦PaperLength=1000¦PaperWidth=1000¦Scale=100¦PaperSource=15¦PrintQuality=600¦MediaType=1¦DitherType=10¦PaperKind=Letter¦PrintScaleMode=1
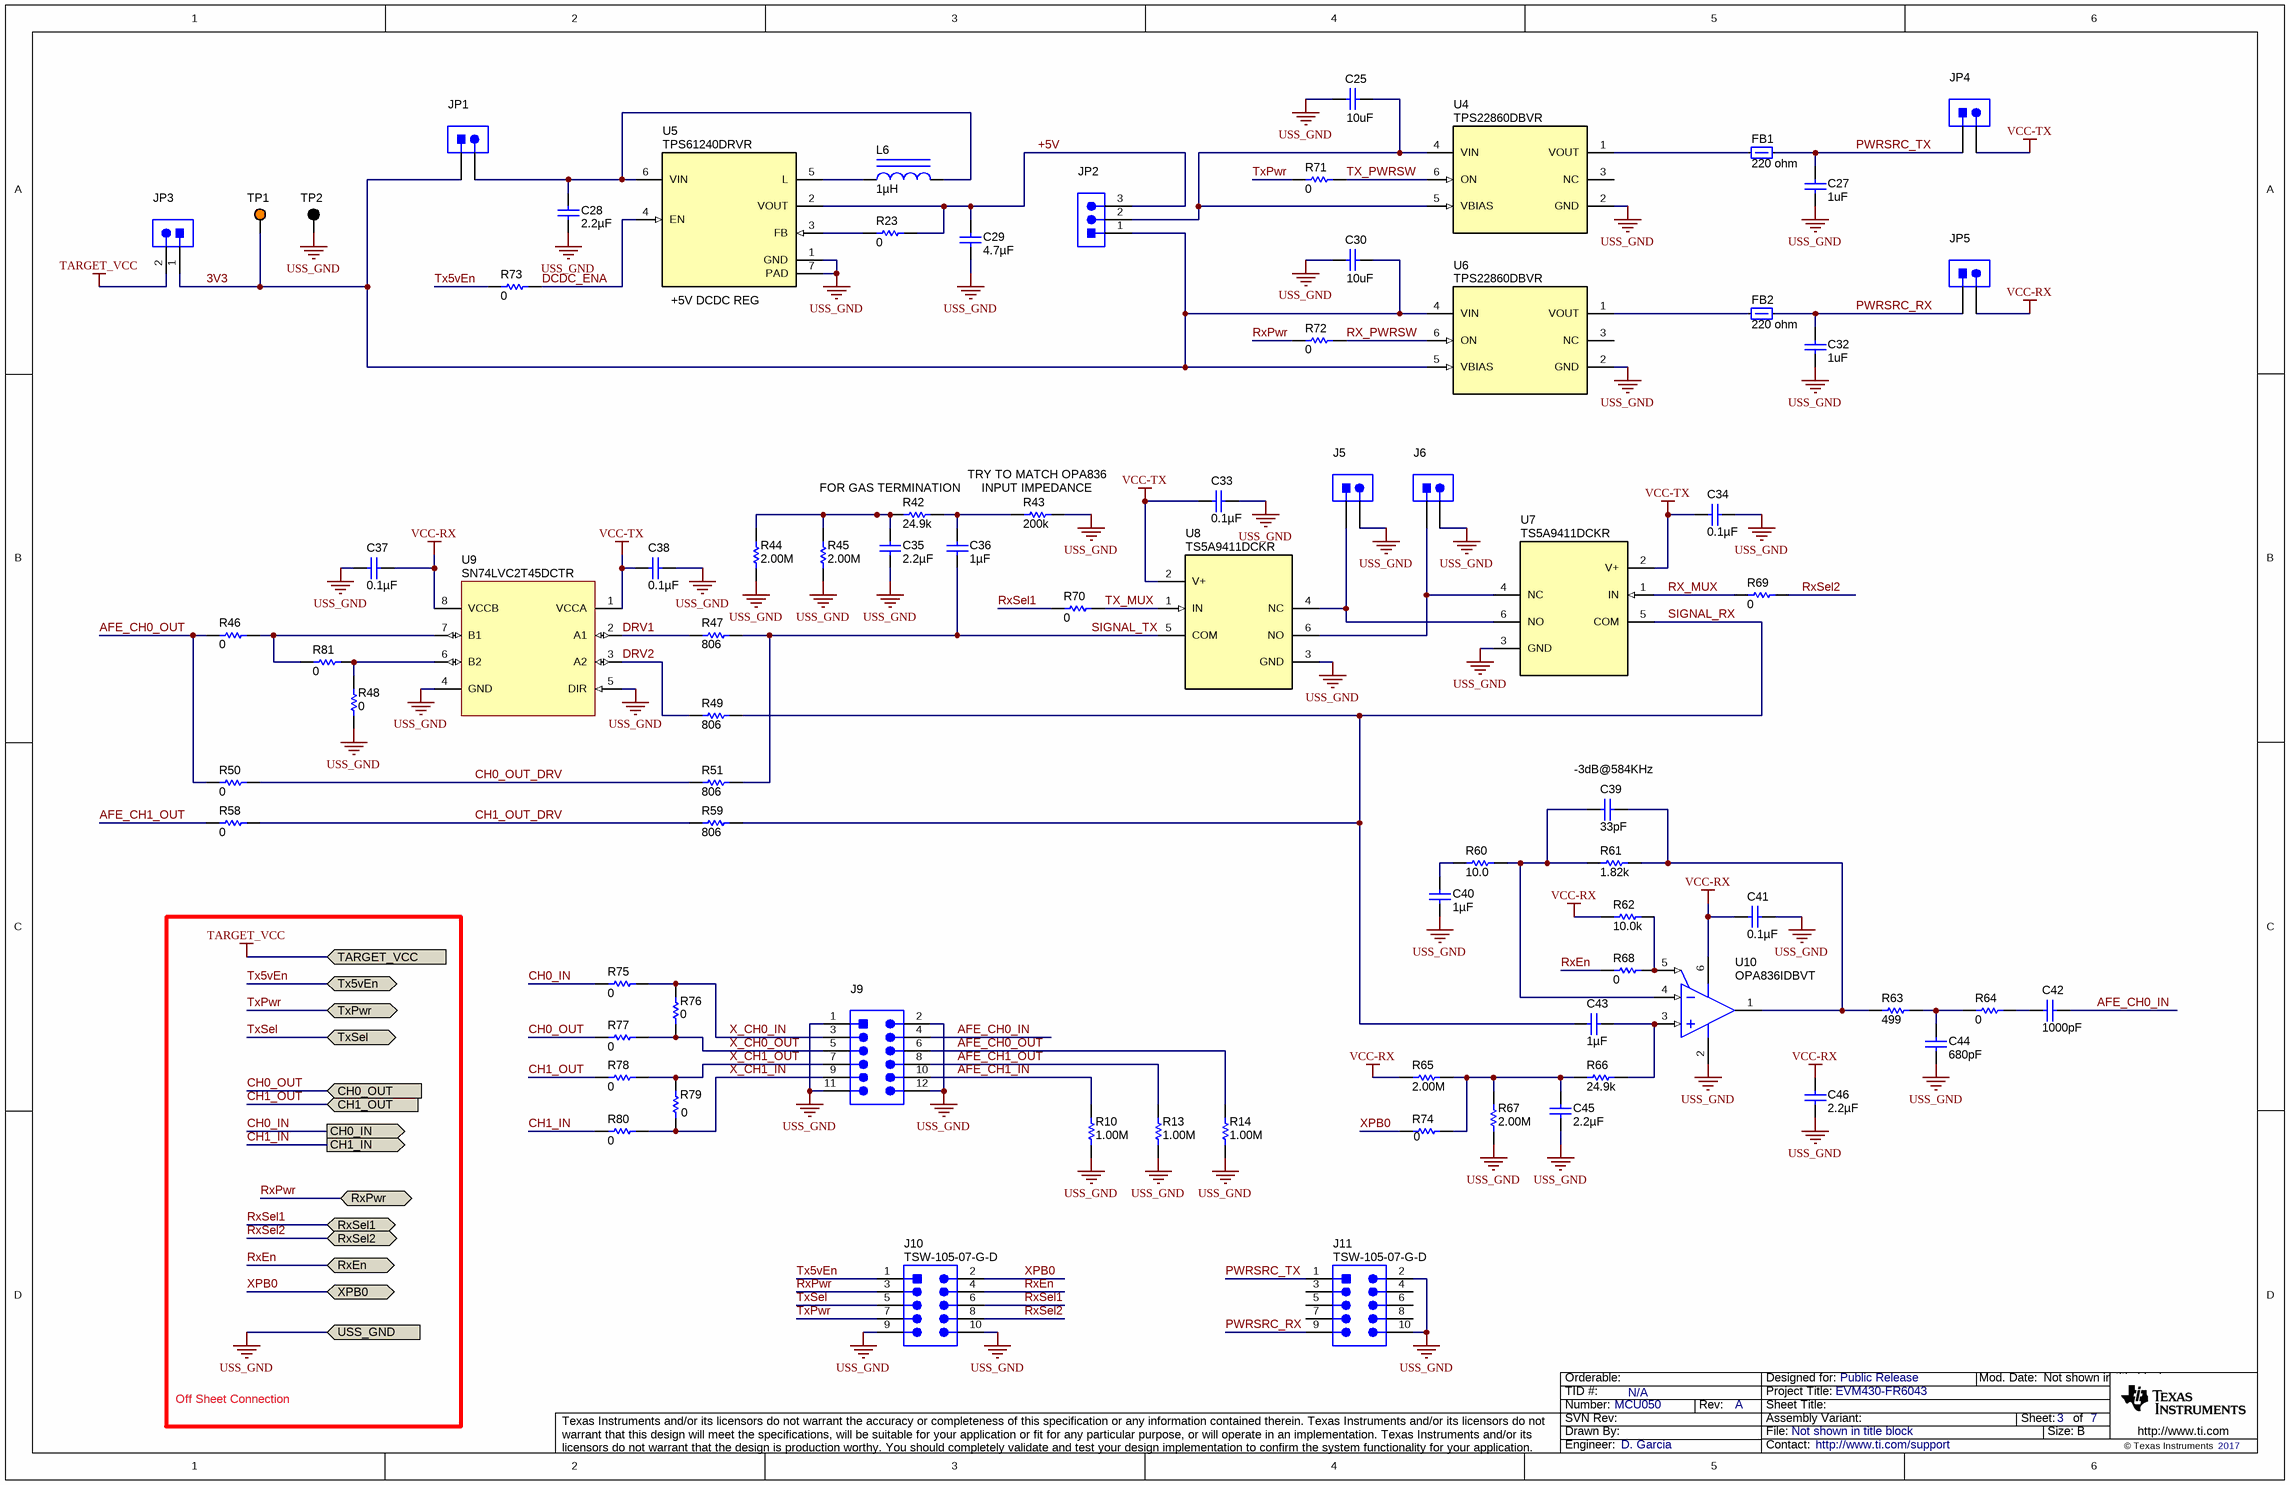
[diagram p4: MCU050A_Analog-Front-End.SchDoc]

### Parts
C25  value 10uF  [0805_HV]  (hidden comment: GRM219R61A106KE44D)
C27  value 1uF  [0805_HV]  (hidden comment: GRM21BR61C105KA01L)
C28  ValueDisplayed: 2.2µF  [0603]  (hidden comment: GRM188R61C225KE15D)
C29  ValueDisplayed: 4.7µF  [0603]  (hidden comment: GRM188R61C475KAAJ)
C30  value 10uF  [0805_HV]  (hidden comment: GRM219R61A106KE44D)
C32  value 1uF  [0805_HV]  (hidden comment: GRM21BR61C105KA01L)
C33  ValueDisplayed: 0.1µF  [0402]  (hidden comment: GRM155R71C104KA88D)
C34  ValueDisplayed: 0.1µF  [0402]  (hidden comment: GRM155R71C104KA88D)
C35  ValueDisplayed: 2.2µF  [0603L]  (hidden comment: GRM188R61C225KE15D)
C36  ValueDisplayed: 1µF  [0603L]  (hidden comment: GRM188R71C105KA12D)
C37  ValueDisplayed: 0.1µF  [0402]  (hidden comment: GRM155R71C104KA88D)
C38  ValueDisplayed: 0.1µF  [0402]  (hidden comment: GRM155R71C104KA88D)
C39  ValueDisplayed: 33pF  [0603L]  (hidden comment: GRM1885C1H330JA01D)
C40  ValueDisplayed: 1µF  [0603L]  (hidden comment: GRM188R71C105KA12D)
C41  ValueDisplayed: 0.1µF  [0402]  (hidden comment: GRM155R71C104KA88D)
C42  ValueDisplayed: 1000pF  [0603L]  (hidden comment: GRM188R71C102KA01D)
C43  ValueDisplayed: 1µF  [0603L]  (hidden comment: GRM188R71C105KA12D)
C44  ValueDisplayed: 680pF  [0603L]  (hidden comment: GRM1885C1H681JA01D)
C45  ValueDisplayed: 2.2µF  [0603L]  (hidden comment: GRM188R61C225KE15D)
C46  ValueDisplayed: 2.2µF  [0603]  (hidden comment: GRM188R61C225KE15D)
FB1  value 220 ohm  [0603]  (hidden comment: MPZ1608S221A)
FB2  value 220 ohm  [0603]  (hidden comment: MPZ1608S221A)
J5  61300211121  [WURTH_61300211121]  (value not drawn)
J6  61300211121  [WURTH_61300211121]  (value not drawn)
J9  TSW-106-07-G-D  [TSW-106-07-G-D]  (value not drawn)
J10  TSW-105-07-G-D  [TSW-105-07-G-D]
J11  TSW-105-07-G-D  [TSW-105-07-G-D]
JP1  61300211121  [WURTH_61300211121]  (value not drawn)
JP2  61300311121  [WURTH_61300311121]  (value not drawn)
JP3  61300211121  [WURTH_61300211121]  (value not drawn)
JP4  61300211121  [WURTH_61300211121]  (value not drawn)
JP5  61300211121  [WURTH_61300211121]  (value not drawn)
L6  ValueDisplayed: 1µH  [0805_HV]  (hidden comment: LQM21PN1R0MC0D)
R10  ValueDisplayed: 1.00M  [0603L]  (hidden comment: RC0603FR-071ML)
R13  ValueDisplayed: 1.00M  [0603L]  (hidden comment: RC0603FR-071ML)
R14  ValueDisplayed: 1.00M  [0603L]  (hidden comment: RC0603FR-071ML)
R23  ValueDisplayed: 0  [0603L]  (hidden comment: RC0603JR-070RL)
R42  ValueDisplayed: 24.9k  [0603L]  (hidden comment: RC0603FR-0724K9L)
R43  ValueDisplayed: 200k  [0603L]  (hidden comment: RC0603FR-07200KL)
R44  ValueDisplayed: 2.00M  [0603L]  (hidden comment: RC0603FR-072ML)
R45  ValueDisplayed: 2.00M  [0603L]  (hidden comment: RC0603FR-072ML)
R46  ValueDisplayed: 0  [0603L]  (hidden comment: RC0603JR-070RL)
R47  ValueDisplayed: 806  [0603L]  (hidden comment: RC0603FR-07806RL)
R48  ValueDisplayed: 0  [0603L]  (hidden comment: RC0603JR-070RL)
R49  ValueDisplayed: 806  [0603L]  (hidden comment: RC0603FR-07806RL)
R50  ValueDisplayed: 0  [0603L]  (hidden comment: RC0603JR-070RL)
R51  ValueDisplayed: 806  [0603L]  (hidden comment: RC0603FR-07806RL)
R58  ValueDisplayed: 0  [0603L]  (hidden comment: RC0603JR-070RL)
R59  ValueDisplayed: 806  [0603L]  (hidden comment: RC0603FR-07806RL)
R60  ValueDisplayed: 10.0  [0603L]  (hidden comment: RC0603FR-0710RL)
R61  ValueDisplayed: 1.82k  [0603L]  (hidden comment: RC0603FR-071K82L)
R62  ValueDisplayed: 10.0k  [0603L]  (hidden comment: RCG060310K0FKEA)
R63  ValueDisplayed: 499  [0603L]  (hidden comment: RC0603FR-07499RL)
R64  ValueDisplayed: 0  [0603L]  (hidden comment: RC0603JR-070RL)
R65  ValueDisplayed: 2.00M  [0603L]  (hidden comment: RC0603FR-072ML)
R66  ValueDisplayed: 24.9k  [0603L]  (hidden comment: RC0603FR-0724K9L)
R67  ValueDisplayed: 2.00M  [0603L]  (hidden comment: RC0603FR-072ML)
R68  ValueDisplayed: 0  [0603L]  (hidden comment: RC0603JR-070RL)
R69  ValueDisplayed: 0  [0603L]  (hidden comment: RC0603JR-070RL)
R70  ValueDisplayed: 0  [0603L]  (hidden comment: RC0603JR-070RL)
R71  ValueDisplayed: 0  [0603L]  (hidden comment: RC0603JR-070RL)
R72  ValueDisplayed: 0  [0603L]  (hidden comment: RC0603JR-070RL)
R73  ValueDisplayed: 0  [0603L]  (hidden comment: RC0603JR-070RL)
R74  Res_ohm: 0  [0603L]  (hidden comment: RC0603JR-070RL)
R75  ValueDisplayed: 0  [0603L]  (hidden comment: RC0603JR-070RL)
R76  ValueDisplayed: 0  [0603L]  (hidden comment: RC0603JR-070RL)
R77  ValueDisplayed: 0  [0603L]  (hidden comment: RC0603JR-070RL)
R78  ValueDisplayed: 0  [0603L]  (hidden comment: RC0603JR-070RL)
R79  Res_ohm: 0  [0603L]  (hidden comment: RC0603JR-070RL)
R80  ValueDisplayed: 0  [0603L]  (hidden comment: RC0603JR-070RL)
R81  ValueDisplayed: 0  [0603L]  (hidden comment: RCG060310K0FKEA)
TP1  5003  [Keystone5003]  (value not drawn)
TP2  5001  [Keystone5001]  (value not drawn)
U4  TPS22860DBVR  [DBV0006A_N]
U5  TPS61240DRVR  [DRV0006A]
U6  TPS22860DBVR  [DBV0006A_N]
U7  TS5A9411DCKR  [DCK0006A_N]
U8  TS5A9411DCKR  [DCK0006A_N]
U9  SN74LVC2T45DCTR  [DCT0008A_N]
U10  OPA836IDBVT  [DBV0006A_N]

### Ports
CH0_IN (out), CH0_OUT (in), CH1_IN (out), CH1_OUT (in), RxEn (bidir), RxPwr (bidir), RxSel1 (bidir), RxSel2 (bidir), TARGET_VCC, Tx5vEn (bidir), TxPwr (bidir), TxSel (bidir), USS_GND, XPB0 (bidir)

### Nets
TARGET_VCC: JP3.2 ; port TARGET_VCC
USS_GND: C25.2 C27.2 C28.2 C29.2 C30.2 C32.2 C33.1 C34.1 C35.1 C37.2 C38.1 C40.1 C41.1 C44.2 C45.1 C46.2 J5.2 J6.2 J9.1 J9.2 J9.11 J9.12 J10.9 J10.10 J11.2 J11.10 R10.1 R13.1 R14.1 R43.2 R44.1 R45.1 R48.1 R67.1 TP2.1 U4.2(GND) U5.1(GND) U5.7(PAD) U6.2(GND) U7.3(GND) U8.3(GND) U9.4(GND) U9.5(DIR) U10.2(VS-) ; port USS_GND
VCC-RX: C37.1 C41.2 C46.1 JP5.2 R62.1 R65.2 U9.8(VCCB) U10.6(VS+)
VCC-TX: C33.2 C34.2 C38.2 JP4.2 U7.2(V+) U8.2(V+) U9.1(VCCA)
3V3: C30.1 JP1.1 JP2.1 JP3.1 TP1.1 U6.4(VIN) U6.5(VBIAS)
+5V: C29.1 JP2.3 R23.1 U5.2(VOUT)
AFE_CH0_IN: C42.1 J9.4
AFE_CH0_OUT: J9.6 R14.2 R46.1 R50.1
AFE_CH1_IN: J9.10 R10.2
AFE_CH1_OUT: J9.8 R13.2 R58.1
CH0_IN: R75.1 ; port CH0_IN
CH0_OUT: R77.1 ; port CH0_OUT
CH0_OUT_DRV: R50.2 R51.1
CH1_IN: R80.1 ; port CH1_IN
CH1_OUT: R78.1 ; port CH1_OUT
CH1_OUT_DRV: R58.2 R59.1
DCDC_ENA: R73.1 U5.4(EN)
DRV1: R47.1 U9.2(A1)
DRV2: R49.1 U9.3(A2)
PWRSRC_RX: C32.1 FB2.2 J11.9 JP5.1
PWRSRC_TX: C27.1 FB1.2 J11.1 JP4.1
RX_MUX: R69.2 U7.1(IN)
RX_PWRSW: R72.1 U6.6(ON)
RxEn: J10.4 R68.2 ; port RxEn
RxPwr: J10.3 R72.2 ; port RxPwr
RxSel1: J10.6 R70.2 ; port RxSel1
RxSel2: J10.8 R69.1 ; port RxSel2
SIGNAL_RX: C43.1 R49.2 R59.2 U7.5(COM)
SIGNAL_TX: C36.1 R47.2 R51.2 U8.5(COM)
Tx5vEn: J10.1 R73.2 ; port Tx5vEn
TX_MUX: R70.1 U8.1(IN)
TX_PWRSW: R71.1 U4.6(ON)
TxPwr: J10.7 R71.2 ; port TxPwr
TxSel: J10.5 ; port TxSel
X_CH0_IN: J9.3 R75.2 R76.2
X_CH0_OUT: J9.5 R76.1 R77.2
X_CH1_IN: J9.9 R79.1 R80.2
X_CH1_OUT: J9.7 R78.2 R79.2
XPB0: J10.2 R74.2 ; port XPB0
NetC25_1: C25.1 JP2.2 U4.4(VIN) U4.5(VBIAS)
NetC28_1: C28.1 JP1.2 L6.2 U5.6(VIN)
NetC35_2: C35.2 R42.1 R44.2 R45.2
NetC36_2: C36.2 R42.2 R43.1
NetC39_1: C39.1 R61.2 R63.1 U10.1(VOUT)
NetC39_2: C39.2 R60.2 R61.1 U10.4(VIN-)
NetC40_2: C40.2 R60.1
NetC42_2: C42.2 R64.1
NetC43_2: C43.2 R66.2 U10.3(VIN+)
NetC44_1: C44.1 R63.2 R64.2
NetC45_2: C45.2 R65.1 R66.1 R67.2 R74.1
NetFB1_1: FB1.1 U4.1(VOUT)
NetFB2_1: FB2.1 U6.1(VOUT)
NetJ5_1: J5.1 U7.6(NO) U8.4(NC)
NetJ6_1: J6.1 U7.4(NC) U8.6(NO)
NetL6_1: L6.1 U5.5(L)
NetR23_2: R23.2 U5.3(FB)
NetR46_2: R46.2 R81.2 U9.7(B1)
NetR48_2: R48.2 R81.1 U9.6(B2)
NetR62_2: R62.2 R68.1 U10.5(~{PD})

Not connected (* = marked no-connect by the designer): J11 3 4 5 6 7 8; U4 3(NC); U6 3(NC)

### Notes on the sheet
- (near U5) +5V DCDC REG
- (near R42) FOR GAS TERMINATION
- (near R43) TRY TO MATCH OPA836
- (near R43) INPUT IMPEDANCE
- (near C39) -3dB@584KHz
- Off Sheet Connection

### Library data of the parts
C25 C30 = CMP-0008196-2: CAP, CERM, 10 uF, 10 V, +/- 10%, X5R, 0805; Manufacturer: MuRata; TaMin_C: -55°C; ESR_ohm: 5m; Polarized: N; SizeAreaWB_mm2: 6.75; Value1: 0.005 ohm; U/M: EA; TaMax_C: 85°C; SizeZ_mm: 1.45; SizeX_mm: 2; SizeY_mm: 1.25; Cap_Case: 0805; Value2: 10V; SizeArea_mm2: 2.5; CompType: Capacitor; Cap_F: 10µF; AEC Category: Q200
C27 C32 = CMP-0008291-2: CAP, CERM, 1 uF, 16 V, +/- 10%, X5R, 0805; Manufacturer: MuRata; TaMin_C: -55°C; Polarized: N; SizeAreaWB_mm2: 6.75; Value1: Unknown; U/M: EA; TaMax_C: 85°C; SizeZ_mm: 1.45; SizeX_mm: 2; SizeY_mm: 1.25; Cap_Case: 0805; Value2: 16V; SizeArea_mm2: 2.5; CompType: Capacitor; Cap_F: 1µF; AEC Category: Q200
C28 C46 = GRM188R61C225KE15D: CAP, CERM, 2.2 µF, 16 V, +/- 10%, X5R, 0603; Manufacturer: MuRata; Polarized: N; CompType: Capacitor; Value: 2.2uF; U/M: EA; Cap_F: 0.0000022; Tolerance_%: 10; Value1: Unknown; VDC_V: 16; Value2: 16V; TaMin_C: -55; TaMax_C: 85
C29 = GRM188R61C475KAAJ: CAP, CERM, 4.7 µF, 16 V, +/- 10%, X5R, 0603; Manufacturer: MuRata; Polarized: N; CompType: Capacitor; Value: 4.7uF; U/M: EA; Cap_F: 0.0000047; Tolerance_%: 10; Value1: Unknown; VDC_V: 16; Value2: 16V; TaMin_C: -55; TaMax_C: 85; AEC Category: Q200
C33 C34 C37 C38 C41 = GRM155R71C104KA88D: CAP, CERM, 0.1 µF, 16 V, +/- 10%, X7R, 0402; Manufacturer: MuRata; Value: 0.1uF; Polarized: N; CompType: Capacitor; U/M: EA; Cap_F: 0.0000001; Tolerance_%: 10; Value1: Unknown; VDC_V: 16; Value2: 16V; TaMin_C: -55; TaMax_C: 125; AEC Category: Q200
C35 C45 = GRM188R61C225KE15D: CAP, CERM, 2.2 µF, 16 V, +/- 10%, X5R, 0603; Manufacturer: MuRata; Polarized: N; CompType: Capacitor; Value: 2.2uF; U/M: EA; Cap_F: 0.0000022; Tolerance_%: 10; Value1: Unknown; VDC_V: 16; Value2: 16V; TaMin_C: -55; TaMax_C: 85; Cap_Case: 0603
C36 C40 C43 = GRM188R71C105KA12D: CAP, CERM, 1 µF, 16 V, +/- 10%, X7R, 0603; Manufacturer: MuRata; Polarized: N; CompType: Capacitor; Value: 1uF; U/M: EA; Cap_F: 0.000001; Tolerance_%: 10; ESR_ohm: 0.011; Value1: 0.011 ohm; VDC_V: 16; Value2: 16V; TaMin_C: -55; TaMax_C: 125; Cap_Case: 0603
C39 = GRM1885C1H330JA01D: CAP, CERM, 33 pF, 50 V, +/- 5%, C0G/NP0, 0603; Manufacturer: MuRata; Polarized: N; CompType: Capacitor; Value: 33pF; U/M: EA; Cap_F: 0.000000000033; Tolerance_%: 5; Value1: Unknown; VDC_V: 50; Value2: 50V; TaMin_C: -55; TaMax_C: 125; Cap_Case: 0603; AEC Category: Q200
C42 = GRM188R71C102KA01D: CAP, CERM, 1000 pF, 16 V,+/- 10%, X7R, 0603; Manufacturer: MuRata; Polarized: N; CompType: Capacitor; Value: 1000pF; U/M: EA; Cap_F: 0.000000001; Tolerance_%: 10; VDC_V: 16; Value2: 16V; TaMin_C: -55; TaMax_C: 125; Cap_Case: 0603; SizeArea_mm2: 1.28; SizeAreaWB_mm2: 4.68; SizeX_mm: 1.6; SizeY_mm: 0.8; SizeZ_mm: 1; AEC Category: Q200; Green_Lifecycle: Active; Green_REACh: Passed
C44 = GRM1885C1H681JA01D: CAP, CERM, 680 pF, 50 V, +/- 5%, C0G/NP0, 0603; Manufacturer: MuRata; Polarized: N; CompType: Capacitor; Value: 680pF; U/M: EA; Cap_F: 0.00000000068; Tolerance_%: 5; Value1: Unknown; VDC_V: 50; Value2: 50V; TaMin_C: -55; TaMax_C: 125; Cap_Case: 0603; AEC Category: Q200
FB1 FB2 = MPZ1608S221A: Ferrite Bead, 220 ohm @ 100 MHz, 2.2 A, 0603; Manufacturer: TDK; Alternate PartNumber: MPZ1608S221ATA00; Imax_A: 2.2; DCR_ohm: 0.05; Value1: 0.05 ohm; Value2: 2.2A; ZTyp@100MHz_Ohm: 220
J5 J6 JP1 JP3-JP5 = 61300211121: as J30 on sheet MCU050A_main
J9 = CMP-0075412-1: Header, 100mil, 6x2, Gold, TH; Manufacturer: Samtec; Pitch_mm: 2.54; Cert_VDE: N; Gender: Male; Cert_CSA: Y; Voltage_V: 550V; Green_REACh: Passed; Current_A: 6.3A; CT: False; Green_Lifecycle: Active; Row_Count: 2; CNHeader: True
J10 J11 = TSW-105-07-G-D: as J1 on sheet MCU050A_EVM430-FR6043
JP2 = 61300311121: as J4 on sheet MCU050A_EVM430-FR6043
L6 = LQM21PN1R0MC0D: Inductor, Multilayer, Ferrite, 1 µH, 0.8 A, 0.19 ohm, SMD; Manufacturer: MuRata; Value: 1uH; Ind_H: 1.0E-6; Imax_A: 0.8; Irms: 0.8A @ 40C rise; DCR_ohm: 0.19; Value2: 0.8A; AEC Category: Q200
R10 R13 R14 = CMP-0022899-2: RES, 1.00 M, 1%, 0.1 W, 0603; Manufacturer: Yageo America; Power_W: 100mW; TempCo: 200 ppm/C; Value_Code: 1M00; U/M: EA; Value: 1.00Meg; EIA_Code: E96; Res_ohm: 1M; SizeX_mm: 1.6; SizeY_mm: 0.8; SizeZ_mm: 1; Value2: 0.1W; SizeArea_mm2: 1.28; CompType: Resistor; VDC_V: 150V; AEC Category: Q200
R23 R46 R48 R50 R58 R64 R68-R73 R75-R80 = RC0603JR-070RL: RES, 0, 5%, 0.1 W, 0603; Manufacturer: Yageo America; CompType: Resistor; Value: 0; Value_Code: 0000; Tolerance_%: 5; Power_W: 0.1; Value2: 0.1W; VDC_V: 50; TempCo: 200 ppm/C; EIA_Code: E24; U/M: EA
R42 R66 = RC0603FR-0724K9L: RES, 24.9 k, 1%, 0.1 W, 0603; Manufacturer: Yageo America; CompType: Resistor; Value: 24.9k; Res_ohm: 24900; Value_Code: 24k9; Tolerance_%: 1; Power_W: 0.1; Value2: 0.1W; VDC_V: 150; TempCo: 200 ppm/C; EIA_Code: E96; U/M: EA; AEC Category: Q200
R43 = RC0603FR-07200KL: RES, 200 k, 1%, 0.1 W, 0603; Manufacturer: Yageo America; CompType: Resistor; Value: 200k; Res_ohm: 200000; Tolerance_%: 1; Power_W: 0.1; Value2: 0.1W; VDC_V: 150; TempCo: 200 ppm/C; SizeArea_mm2: 1.28; SizeX_mm: 1.6; SizeY_mm: 0.8; EIA_Code: E96; U/M: EA; AEC Category: Q200
R44 R45 R65 R67 = RC0603FR-072ML: RES, 2.00 M, 1%, 0.1 W, 0603; Manufacturer: Yageo America; CompType: Resistor; Value: 2.00Meg; Res_ohm: 2000000; Value_Code: 2M00; Tolerance_%: 1; Power_W: 0.1; Value2: 0.1W; VDC_V: 150; TempCo: 200 ppm/C; SizeArea_mm2: 1.28; SizeX_mm: 1.6; SizeY_mm: 0.8; EIA_Code: E96; U/M: EA; AEC Category: Q200
R47 R49 R51 R59 = RC0603FR-07806RL: RES, 806, 1%, 0.1 W, 0603; Manufacturer: Yageo America; CompType: Resistor; Value: 806; Value_Code: 806R; Tolerance_%: 1; Power_W: 0.1; Value2: 0.1W; VDC_V: 150; TempCo: 200 ppm/C; EIA_Code: E96; U/M: EA; AEC Category: Q200
R60 = RC0603FR-0710RL: RES, 10.0, 1%, 0.1 W, 0603; Manufacturer: Yageo America; CompType: Resistor; Value: 10.0; Res_ohm: 10; Value_Code: 10R0; Tolerance_%: 1; Power_W: 0.1; Value2: 0.1W; VDC_V: 150; TempCo: 200 ppm/C; EIA_Code: E96; U/M: EA; AEC Category: Q200
R61 = RC0603FR-071K82L: RES, 1.82 k, 1%, 0.1 W, 0603; Manufacturer: Yageo America; CompType: Resistor; Value: 1.82k; Res_ohm: 1820; Value_Code: 1k82; Tolerance_%: 1; Power_W: 0.1; Value2: 0.1W; VDC_V: 150; TempCo: 200 ppm/C; EIA_Code: E96; U/M: EA; AEC Category: Q200
R62 R81 = RCG060310K0FKEA: RES, 10.0 k, 1%, 0.1 W, 0603; Manufacturer: Vishay Draloric; CompType: Resistor; Value: 10.0k; Res_ohm: 10000; Value_Code: 10k0; Tolerance_%: 1; Power_W: 0.1; Value2: 0.1W; VDC_V: 75; TempCo: 100 ppm/C; EIA_Code: E96; U/M: EA; AEC Category: Q200; AEC Qualified: N
R63 = RC0603FR-07499RL: RES, 499, 1%, 0.1 W, 0603; Manufacturer: Yageo America; CompType: Resistor; Value: 499; Value_Code: 499R; Tolerance_%: 1; Power_W: 0.1; Value2: 0.1W; VDC_V: 150; TempCo: 200 ppm/C; EIA_Code: E96; U/M: EA; AEC Category: Q200
R74 = RC0603JR-070RL: RES, 0, 5%, 0.1 W, 0603; Manufacturer: Yageo America; CompType: Resistor; Value: 0; ValueDisplayed: DNI; Value_Code: 0000; Tolerance_%: 5; Power_W: 0.1; Value2: 0.1W; VDC_V: 50; TempCo: 200 ppm/C; EIA_Code: E24; U/M: EA
TP1 = 5003: Test Point, Miniature, Orange, TH; Manufacturer: Keystone; CompType: Test Point Loop; U/M: EA
TP2 = 5001: Test Point, Miniature, Black, TH; Manufacturer: Keystone; CompType: Test Point Loop; U/M: EA
U4 U6 = TPS22860DBVR: Ultra-Low Leakage Load Switch, DBV0006A; Manufacturer: Texas Instruments; SymbolCreator: Altium; CompType: IC; U/M: EA
U5 = TPS61240DRVR: 3.5-MHz High Efficiency Step-Up Converter,  DRV0006A; Alternate PartNumber: TPS61240DRVT; Manufacturer: Texas Instruments; SymbolCreator: a799628; CompType: IC; U/M: EA
U7 U8 = TS5A9411DCKR: 10-Ω SPDT ANALOG SWITCH SINGLE-CHANNEL 2:1 MULTIPLEXER/DEMULTIPLEXER, DCK0006A; Alternate PartNumber: TS5A9411DCKT; Manufacturer: Texas Instruments; SymbolCreator: a0411947; SizeArea_mm2: 4.2; SizeAreaWB_mm2: 9.3; SizeX_mm: 2.1; SizeY_mm: 2; SizeZ_mm: 1.1; CompType: IC; U/M: EA
U9 = SN74LVC2T45DCTR: Dual-Bit Dual-Supply Bus Transceiver With Configurable Voltage Translation and 3-State Outputs, DCT0008A; Alternate PartNumber: SN74LVC2T45DCTT; Manufacturer: Texas Instruments; SymbolCreator: Altium; CompType: IC; U/M: EA
U10 = OPA836IDBVT: Very Low Power, Rail to Rail Out, Negative Rail In, VFB Operational Amplifier, 2.5 to 5.5 V, -40 to 125 degC, 6-pin SOT23 (DBV6), Green (RoHS & no Sb/Br); Alternate Manufacturer: Texas Instruments; Alternate PartNumber: Equivalent; 2nd Harmonic(dBc): 85; 3rd Harmonic(dBc): 105; @ MHz: 1; BW @ Acl(MHz): 205; Iib(Max)(nA): 1000; Io(Typ)(mA): 50; Settling Time (0.1%)(Typ)(ns): 30; Slew Rate(Typ)(V/us): 560; Sub Family: Audio Operational Amplifier, High Output Current Amplifier (>=50mA), High Speed Amplifier (>=50MHz), Low Noise Amp (<=10nV/rtHz), Low Offset Voltage Amplifier (<=500uV), Low Supply Voltage Amplifier (<=2.7V); Vio(Max)(mV): 0.4; Vn at Flatband(Typ)(nV/rtHz): 4.6; Vs(Max)(V): 5.5; Vs(Min)(V): 2.5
